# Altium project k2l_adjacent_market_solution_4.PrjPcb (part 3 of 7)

## Sheet k2l_soc_09.SchDoc
size 431 x 279 mm; Date: Not shown in title block; ApprovedBy: Not shown in title block; CheckedBy: Not shown in title block; Author: Not shown in title block; CompanyName: Not shown in title block; Engineer: Not shown in title block; Organization: Not shown in title block; Address1: Not shown in title block; Address2: Not shown in title block; Address3: Not shown in title block; Address4: Not shown in title block; DocumentNumber: 15; Revision: Use project parameter SCH_Rev; SheetNumber: 15; SheetTotal: 38; PageSetup: Record=PageOptions¦CenterHorizontal=True¦CenterVertical=True¦PrintScale=1.00¦XCorrection=1.00¦YCorrection=1.00¦PrintKind=0¦BorderSize=5000000¦LeftOffset=0¦BottomOffset=0¦Orientation=2¦PaperLength=1000¦PaperWidth=1000¦Scale=100¦PaperSource=15¦PrintQuality=600¦MediaType=1¦DitherType=10¦PaperKind=Letter¦PrintScaleMode=1
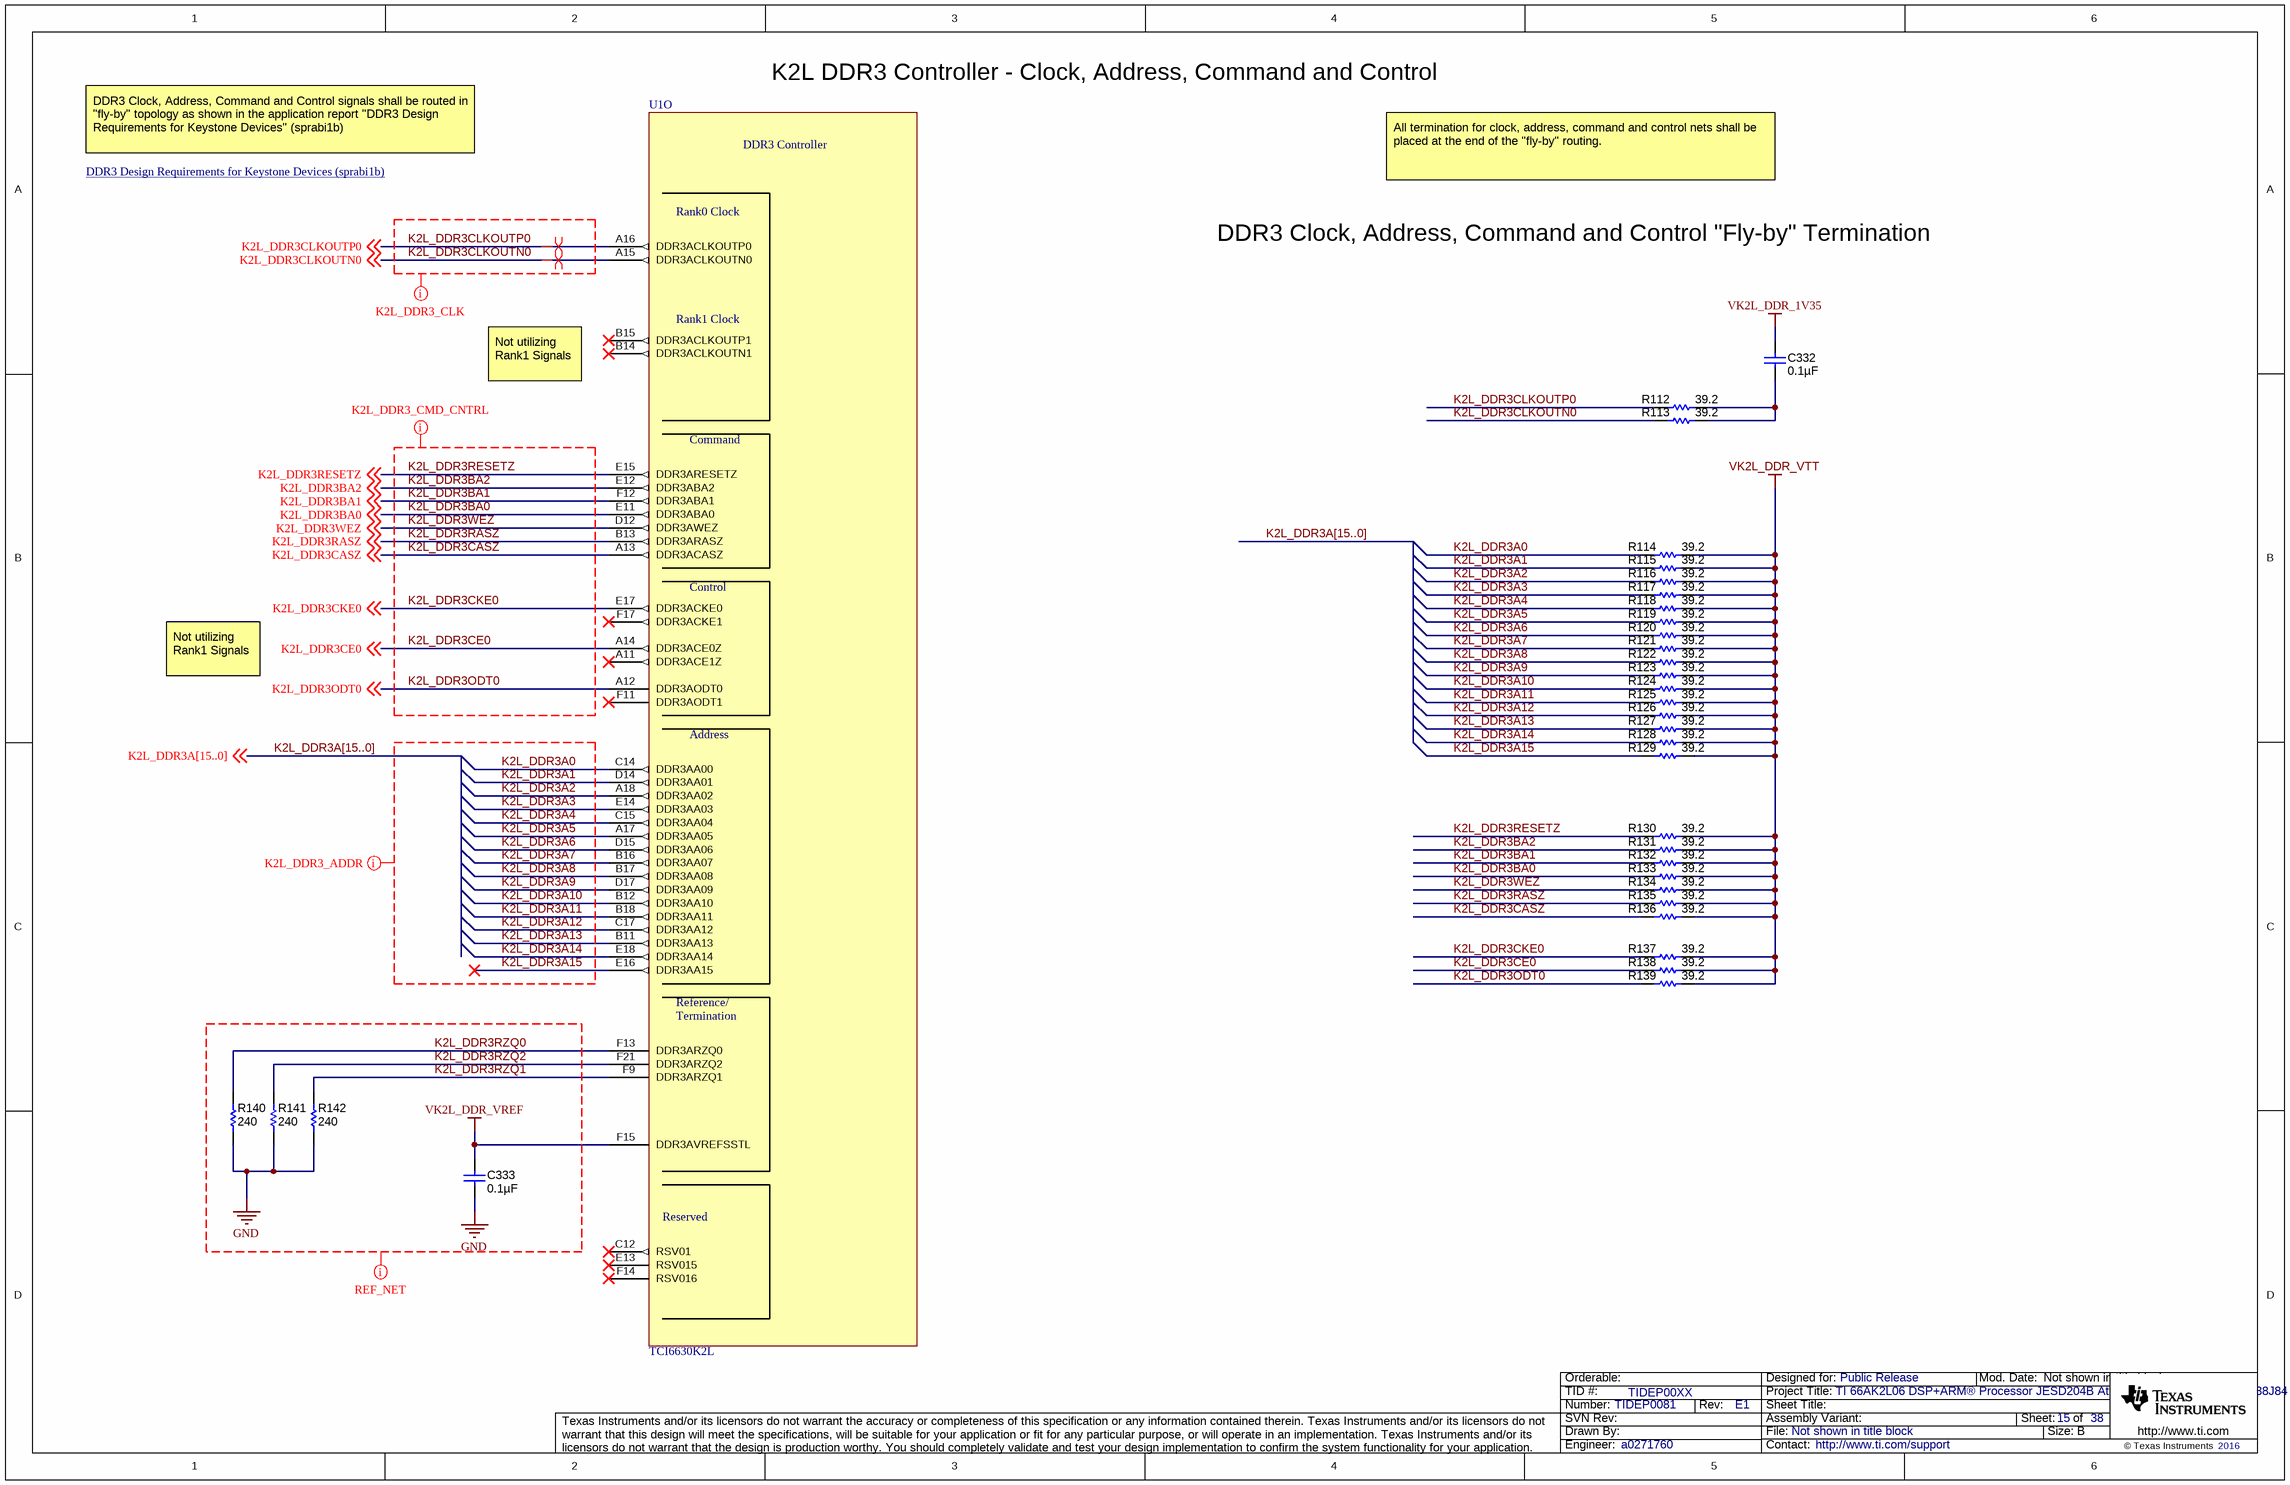
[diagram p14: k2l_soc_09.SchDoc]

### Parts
C332  ValueDisplayed: 0.1µF  [0402]  (hidden comment: GRM152B30J104KE19)
C333  ValueDisplayed: 0.1µF  [0201]  (hidden comment: C0603X5R0J104K030BC)
R112  ValueDisplayed: 39.2  [0402]  (hidden comment: CRCW040239R2FKED)
R113  ValueDisplayed: 39.2  [0402]  (hidden comment: CRCW040239R2FKED)
R114  ValueDisplayed: 39.2  [0402]  (hidden comment: CRCW040239R2FKED)
R115  ValueDisplayed: 39.2  [0402]  (hidden comment: CRCW040239R2FKED)
R116  ValueDisplayed: 39.2  [0402]  (hidden comment: CRCW040239R2FKED)
R117  ValueDisplayed: 39.2  [0402]  (hidden comment: CRCW040239R2FKED)
R118  ValueDisplayed: 39.2  [0402]  (hidden comment: CRCW040239R2FKED)
R119  ValueDisplayed: 39.2  [0402]  (hidden comment: CRCW040239R2FKED)
R120  ValueDisplayed: 39.2  [0402]  (hidden comment: CRCW040239R2FKED)
R121  ValueDisplayed: 39.2  [0402]  (hidden comment: CRCW040239R2FKED)
R122  ValueDisplayed: 39.2  [0402]  (hidden comment: CRCW040239R2FKED)
R123  ValueDisplayed: 39.2  [0402]  (hidden comment: CRCW040239R2FKED)
R124  ValueDisplayed: 39.2  [0402]  (hidden comment: CRCW040239R2FKED)
R125  ValueDisplayed: 39.2  [0402]  (hidden comment: CRCW040239R2FKED)
R126  ValueDisplayed: 39.2  [0402]  (hidden comment: CRCW040239R2FKED)
R127  ValueDisplayed: 39.2  [0402]  (hidden comment: CRCW040239R2FKED)
R128  ValueDisplayed: 39.2  [0402]  (hidden comment: CRCW040239R2FKED)
R129  ValueDisplayed: 39.2  [0402]  (hidden comment: CRCW040239R2FKED)
R130  ValueDisplayed: 39.2  [0402]  (hidden comment: CRCW040239R2FKED)
R131  ValueDisplayed: 39.2  [0402]  (hidden comment: CRCW040239R2FKED)
R132  ValueDisplayed: 39.2  [0402]  (hidden comment: CRCW040239R2FKED)
R133  ValueDisplayed: 39.2  [0402]  (hidden comment: CRCW040239R2FKED)
R134  ValueDisplayed: 39.2  [0402]  (hidden comment: CRCW040239R2FKED)
R135  ValueDisplayed: 39.2  [0402]  (hidden comment: CRCW040239R2FKED)
R136  ValueDisplayed: 39.2  [0402]  (hidden comment: CRCW040239R2FKED)
R137  ValueDisplayed: 39.2  [0402]  (hidden comment: CRCW040239R2FKED)
R138  ValueDisplayed: 39.2  [0402]  (hidden comment: CRCW040239R2FKED)
R139  ValueDisplayed: 39.2  [0402]  (hidden comment: CRCW040239R2FKED)
R140  ValueDisplayed: 240  [0402]  (hidden comment: CRCW0402240RJNED)
R141  ValueDisplayed: 240  [0402]  (hidden comment: CRCW0402240RJNED)
R142  ValueDisplayed: 240  [0402]  (hidden comment: CRCW0402240RJNED)
U1  TCI6630K2L  [BGA900C80P30X30_2500X2500X355]  (part O of 24)

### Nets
GND: C333.2 R140.1 R141.1 R142.1  [project net DAC_OUT0N_T1]
VK2L_DDR_1V35: C332.1
VK2L_DDR_VREF: C333.1 U1.F15(DDR3AVREFSSTL)
VK2L_DDR_VTT: R114.2 R115.2 R116.2 R117.2 R118.2 R119.2 R120.2 R121.2 R122.2 R123.2 R124.2 R125.2 R126.2 R127.2 R128.2 R129.2 R130.2 R131.2 R132.2 R133.2 R134.2 R135.2 R136.2 R137.2 R138.2 R139.2
K2L_DDR3A0: R114.1 U1.C14(DDR3AA00)
K2L_DDR3A1: R115.1 U1.D14(DDR3AA01)
K2L_DDR3A2: R116.1 U1.A18(DDR3AA02)
K2L_DDR3A3: R117.1 U1.E14(DDR3AA03)
K2L_DDR3A4: R118.1 U1.C15(DDR3AA04)
K2L_DDR3A5: R119.1 U1.A17(DDR3AA05)
K2L_DDR3A6: R120.1 U1.D15(DDR3AA06)
K2L_DDR3A7: R121.1 U1.B16(DDR3AA07)
K2L_DDR3A8: R122.1 U1.B17(DDR3AA08)
K2L_DDR3A9: R123.1 U1.D17(DDR3AA09)
K2L_DDR3A10: R124.1 U1.B12(DDR3AA10)
K2L_DDR3A11: R125.1 U1.B18(DDR3AA11)
K2L_DDR3A12: R126.1 U1.C17(DDR3AA12)
K2L_DDR3A13: R127.1 U1.B11(DDR3AA13)
K2L_DDR3A14: R128.1 U1.E18(DDR3AA14)
K2L_DDR3A15: R129.1 U1.E16(DDR3AA15)
K2L_DDR3BA0: R133.1 U1.E11(DDR3ABA0) ; off-sheet K2L_DDR3BA0
K2L_DDR3BA1: R132.1 U1.F12(DDR3ABA1) ; off-sheet K2L_DDR3BA1
K2L_DDR3BA2: R131.1 U1.E12(DDR3ABA2) ; off-sheet K2L_DDR3BA2
K2L_DDR3CASZ: R136.1 U1.A13(DDR3ACASZ) ; off-sheet K2L_DDR3CASZ
K2L_DDR3CE0: R138.1 U1.A14(DDR3ACE0Z) ; off-sheet K2L_DDR3CE0
K2L_DDR3CKE0: R137.1 U1.E17(DDR3ACKE0) ; off-sheet K2L_DDR3CKE0
K2L_DDR3CLKOUTN0: R113.1 U1.A15(DDR3ACLKOUTN0) ; off-sheet K2L_DDR3CLKOUTN0
K2L_DDR3CLKOUTP0: R112.1 U1.A16(DDR3ACLKOUTP0) ; off-sheet K2L_DDR3CLKOUTP0
K2L_DDR3ODT0: R139.1 U1.A12(DDR3AODT0) ; off-sheet K2L_DDR3ODT0
K2L_DDR3RASZ: R135.1 U1.B13(DDR3ARASZ) ; off-sheet K2L_DDR3RASZ
K2L_DDR3RESETZ: R130.1 U1.E15(DDR3ARESETZ) ; off-sheet K2L_DDR3RESETZ
K2L_DDR3RZQ0: R140.2 U1.F13(DDR3ARZQ0)
K2L_DDR3RZQ1: R142.2 U1.F9(DDR3ARZQ1)
K2L_DDR3RZQ2: R141.2 U1.F21(DDR3ARZQ2)
K2L_DDR3WEZ: R134.1 U1.D12(DDR3AWEZ) ; off-sheet K2L_DDR3WEZ
NetC332_2: C332.2 R112.2 R113.2

Not connected (* = marked no-connect by the designer): U1 A11(DDR3ACE1Z)* B14(DDR3ACLKOUTN1)* B15(DDR3ACLKOUTP1)* C12(RSV01)* E13(RSV015)* F11(DDR3AODT1)* F14(RSV016)* F17(DDR3ACKE1)*

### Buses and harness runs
bus K2L_DDR3A[15..0]

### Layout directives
differential pair: K2L_DDR3CLKOUTN0, K2L_DDR3CLKOUTP0
net class Undefined: GND, K2L_DDR3A0, K2L_DDR3A1, K2L_DDR3A2, K2L_DDR3A3, K2L_DDR3A4, K2L_DDR3A5, K2L_DDR3A6, K2L_DDR3A7, K2L_DDR3A8, K2L_DDR3A9, K2L_DDR3A10, K2L_DDR3A11, K2L_DDR3A12, K2L_DDR3A13, K2L_DDR3A14, K2L_DDR3A15, K2L_DDR3BA0, K2L_DDR3BA1, K2L_DDR3BA2, K2L_DDR3CASZ, K2L_DDR3CE0, K2L_DDR3CKE0, K2L_DDR3CLKOUTN0, K2L_DDR3CLKOUTP0, K2L_DDR3ODT0, K2L_DDR3RASZ, K2L_DDR3RESETZ, K2L_DDR3RZQ0, K2L_DDR3RZQ1, K2L_DDR3RZQ2, K2L_DDR3WEZ, VK2L_DDR_VREF

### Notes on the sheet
- K2L DDR3 Controller - Clock, Address, Command and Control
- DDR3 Clock, Address, Command and Control signals shall be routed in "fly-by" topology as shown in the application report "DDR3 Design Requirements for Keystone Devices" (sprabi1b)
- DDR3 Design Requirements for Keystone Devices (sprabi1b) <http://www.ti.com/lit/an/sprabi1b/sprabi1b.pdf>
- All termination for clock, address, command and control nets shall be placed at the end of the "fly-by" routing.
- DDR3 Clock, Address, Command and Control "Fly-by" Termination
- Not utilizing Rank1 Signals

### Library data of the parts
C332 = GRM152B30J104KE19: CAP, CERM, 0.1 µF, 6.3 V, +/- 10%, B, 0402; Manufacturer: MuRata; Polarized: N; CompType: Capacitor; Value: 0.1uF; U/M: EA; Cap_F: 0.0000001; Tolerance_%: 10; Value1: Unknown; VDC_V: 6.3; Value2: 6.3V; TaMin_C: -25; TaMax_C: 85
C333 = C0603X5R0J104K030BC: CAP, CERM, 0.1 µF, 6.3 V, +/- 10%, X5R, 0201; Manufacturer: TDK; Polarized: N; CompType: Capacitor; Value: 0.1uF; U/M: EA; Cap_F: 0.0000001; Tolerance_%: 10; Value1: Unknown; VDC_V: 6.3; Value2: 6.3V; TaMin_C: -55; TaMax_C: 85
R112-R139 = CRCW040239R2FKED: RES, 39.2, 1%, 0.063 W, 0402; Manufacturer: Vishay-Dale; CompType: Resistor; Value: 39.2; Value_Code: 39R2; Tolerance_%: 1; Power_W: 0.063; Value2: 0.063W; VDC_V: 50; TempCo: 100 ppm/C; EIA_Code: E96; U/M: EA
R140-R142 = CRCW0402240RJNED: RES, 240, 5%, 0.063 W, 0402; Manufacturer: Vishay-Dale; CompType: Resistor; Value: 240; Value_Code: 240R; Tolerance_%: 5; Power_W: 0.063; Value2: 0.063W; VDC_V: 50; TempCo: 200 ppm/C; EIA_Code: E24; U/M: EA
U1 = lamarr_soc_TCI6630K2L: Smallcell Baseband Processor with 4 C66x DSP Cores / 2 ARM A15 Cores / JESD / CPRI...etc

## Sheet k2l_soc_09_1.SchDoc
size 431 x 279 mm; Date: Not shown in title block; ApprovedBy: Not shown in title block; CheckedBy: Not shown in title block; Author: Not shown in title block; CompanyName: Not shown in title block; Engineer: Not shown in title block; Organization: Not shown in title block; Address1: Not shown in title block; Address2: Not shown in title block; Address3: Not shown in title block; Address4: Not shown in title block; DocumentNumber: 16; Revision: Use project parameter SCH_Rev; SheetNumber: 16; SheetTotal: 38; PageSetup: Record=PageOptions¦CenterHorizontal=True¦CenterVertical=True¦PrintScale=1.00¦XCorrection=1.00¦YCorrection=1.00¦PrintKind=0¦BorderSize=5000000¦LeftOffset=0¦BottomOffset=0¦Orientation=2¦PaperLength=1000¦PaperWidth=1000¦Scale=100¦PaperSource=15¦PrintQuality=600¦MediaType=1¦DitherType=10¦PaperKind=Letter¦PrintScaleMode=1
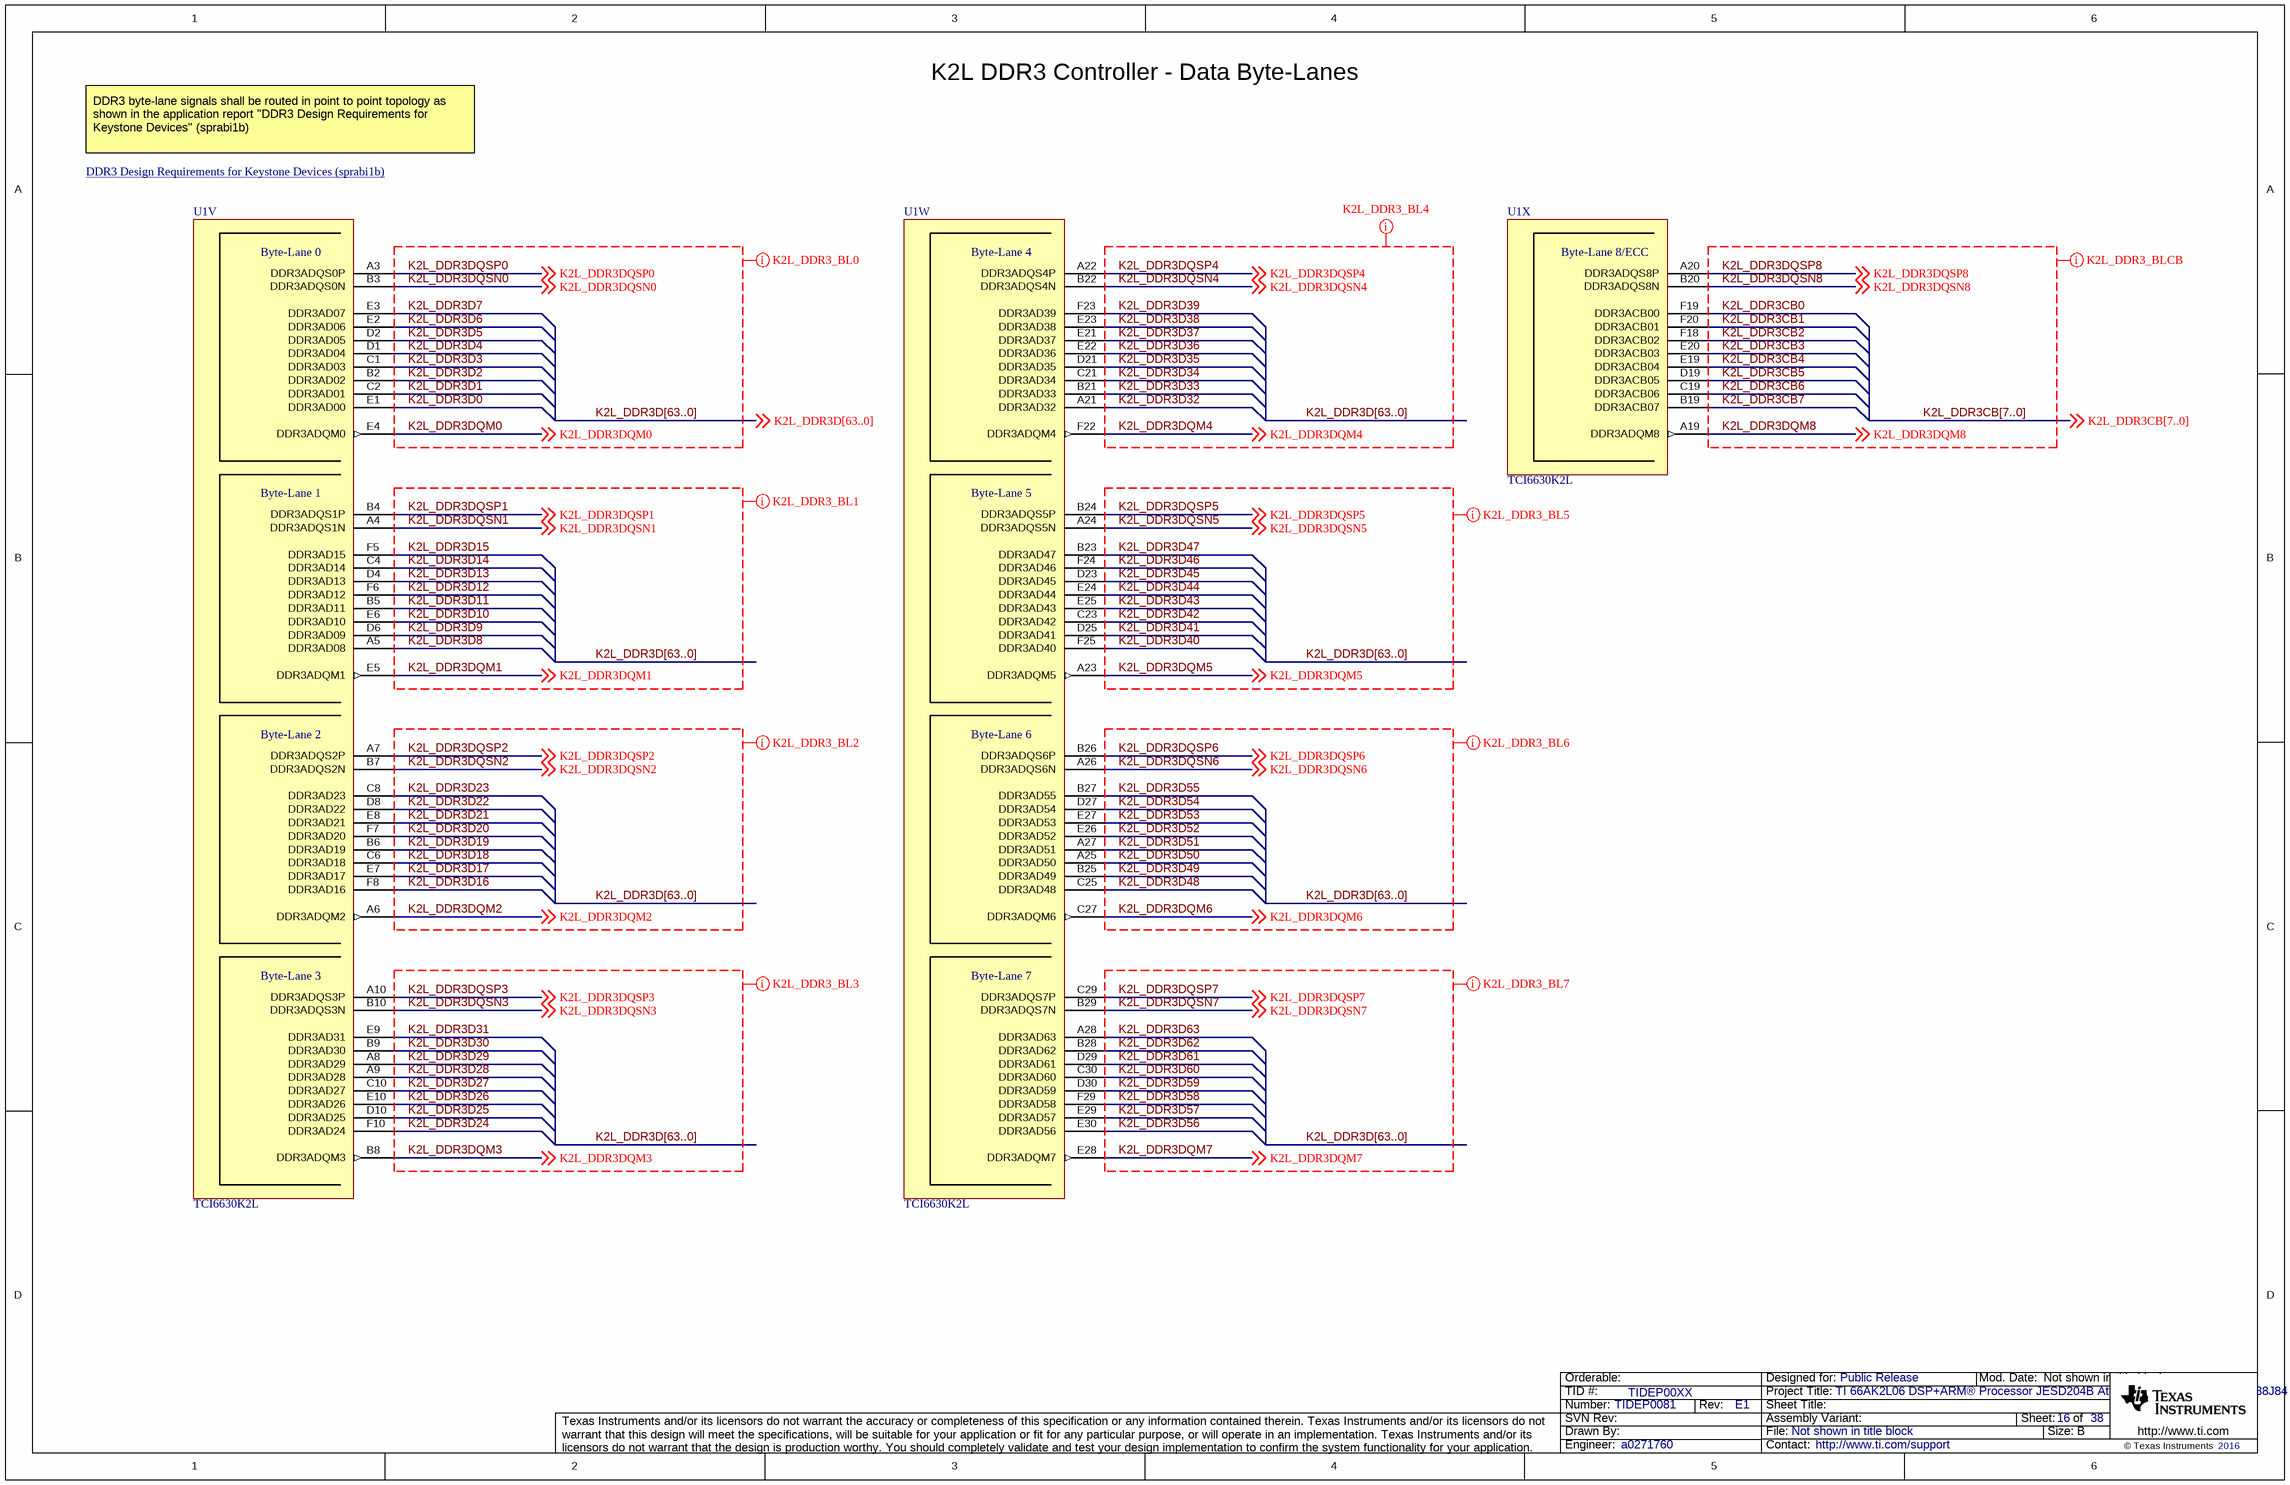
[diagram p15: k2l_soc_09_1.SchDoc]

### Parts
U1  TCI6630K2L  [BGA900C80P30X30_2500X2500X355]  (parts V,W,X of 24)

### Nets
K2L_DDR3CB0: U1.F19(DDR3ACB00)
K2L_DDR3CB1: U1.F20(DDR3ACB01)
K2L_DDR3CB2: U1.F18(DDR3ACB02)
K2L_DDR3CB3: U1.E20(DDR3ACB03)
K2L_DDR3CB4: U1.E19(DDR3ACB04)
K2L_DDR3CB5: U1.D19(DDR3ACB05)
K2L_DDR3CB6: U1.C19(DDR3ACB06)
K2L_DDR3CB7: U1.B19(DDR3ACB07)
K2L_DDR3D0: U1.E1(DDR3AD00)
K2L_DDR3D1: U1.C2(DDR3AD01)
K2L_DDR3D2: U1.B2(DDR3AD02)
K2L_DDR3D3: U1.C1(DDR3AD03)
K2L_DDR3D4: U1.D1(DDR3AD04)
K2L_DDR3D5: U1.D2(DDR3AD05)
K2L_DDR3D6: U1.E2(DDR3AD06)
K2L_DDR3D7: U1.E3(DDR3AD07)
K2L_DDR3D8: U1.A5(DDR3AD08)
K2L_DDR3D9: U1.D6(DDR3AD09)
K2L_DDR3D10: U1.E6(DDR3AD10)
K2L_DDR3D11: U1.B5(DDR3AD11)
K2L_DDR3D12: U1.F6(DDR3AD12)
K2L_DDR3D13: U1.D4(DDR3AD13)
K2L_DDR3D14: U1.C4(DDR3AD14)
K2L_DDR3D15: U1.F5(DDR3AD15)
K2L_DDR3D16: U1.F8(DDR3AD16)
K2L_DDR3D17: U1.E7(DDR3AD17)
K2L_DDR3D18: U1.C6(DDR3AD18)
K2L_DDR3D19: U1.B6(DDR3AD19)
K2L_DDR3D20: U1.F7(DDR3AD20)
K2L_DDR3D21: U1.E8(DDR3AD21)
K2L_DDR3D22: U1.D8(DDR3AD22)
K2L_DDR3D23: U1.C8(DDR3AD23)
K2L_DDR3D24: U1.F10(DDR3AD24)
K2L_DDR3D25: U1.D10(DDR3AD25)
K2L_DDR3D26: U1.E10(DDR3AD26)
K2L_DDR3D27: U1.C10(DDR3AD27)
K2L_DDR3D28: U1.A9(DDR3AD28)
K2L_DDR3D29: U1.A8(DDR3AD29)
K2L_DDR3D30: U1.B9(DDR3AD30)
K2L_DDR3D31: U1.E9(DDR3AD31)
K2L_DDR3D32: U1.A21(DDR3AD32)
K2L_DDR3D33: U1.B21(DDR3AD33)
K2L_DDR3D34: U1.C21(DDR3AD34)
K2L_DDR3D35: U1.D21(DDR3AD35)
K2L_DDR3D36: U1.E22(DDR3AD36)
K2L_DDR3D37: U1.E21(DDR3AD37)
K2L_DDR3D38: U1.E23(DDR3AD38)
K2L_DDR3D39: U1.F23(DDR3AD39)
K2L_DDR3D40: U1.F25(DDR3AD40)
K2L_DDR3D41: U1.D25(DDR3AD41)
K2L_DDR3D42: U1.C23(DDR3AD42)
K2L_DDR3D43: U1.E25(DDR3AD43)
K2L_DDR3D44: U1.E24(DDR3AD44)
K2L_DDR3D45: U1.D23(DDR3AD45)
K2L_DDR3D46: U1.F24(DDR3AD46)
K2L_DDR3D47: U1.B23(DDR3AD47)
K2L_DDR3D48: U1.C25(DDR3AD48)
K2L_DDR3D49: U1.B25(DDR3AD49)
K2L_DDR3D50: U1.A25(DDR3AD50)
K2L_DDR3D51: U1.A27(DDR3AD51)
K2L_DDR3D52: U1.E26(DDR3AD52)
K2L_DDR3D53: U1.E27(DDR3AD53)
K2L_DDR3D54: U1.D27(DDR3AD54)
K2L_DDR3D55: U1.B27(DDR3AD55)
K2L_DDR3D56: U1.E30(DDR3AD56)
K2L_DDR3D57: U1.E29(DDR3AD57)
K2L_DDR3D58: U1.F29(DDR3AD58)
K2L_DDR3D59: U1.D30(DDR3AD59)
K2L_DDR3D60: U1.C30(DDR3AD60)
K2L_DDR3D61: U1.D29(DDR3AD61)
K2L_DDR3D62: U1.B28(DDR3AD62)
K2L_DDR3D63: U1.A28(DDR3AD63)
K2L_DDR3DQM0: U1.E4(DDR3ADQM0) ; off-sheet K2L_DDR3DQM0
K2L_DDR3DQM1: U1.E5(DDR3ADQM1) ; off-sheet K2L_DDR3DQM1
K2L_DDR3DQM2: U1.A6(DDR3ADQM2) ; off-sheet K2L_DDR3DQM2
K2L_DDR3DQM3: U1.B8(DDR3ADQM3) ; off-sheet K2L_DDR3DQM3
K2L_DDR3DQM4: U1.F22(DDR3ADQM4) ; off-sheet K2L_DDR3DQM4
K2L_DDR3DQM5: U1.A23(DDR3ADQM5) ; off-sheet K2L_DDR3DQM5
K2L_DDR3DQM6: U1.C27(DDR3ADQM6) ; off-sheet K2L_DDR3DQM6
K2L_DDR3DQM7: U1.E28(DDR3ADQM7) ; off-sheet K2L_DDR3DQM7
K2L_DDR3DQM8: U1.A19(DDR3ADQM8) ; off-sheet K2L_DDR3DQM8
K2L_DDR3DQSN0: U1.B3(DDR3ADQS0N) ; off-sheet K2L_DDR3DQSN0
K2L_DDR3DQSN1: U1.A4(DDR3ADQS1N) ; off-sheet K2L_DDR3DQSN1
K2L_DDR3DQSN2: U1.B7(DDR3ADQS2N) ; off-sheet K2L_DDR3DQSN2
K2L_DDR3DQSN3: U1.B10(DDR3ADQS3N) ; off-sheet K2L_DDR3DQSN3
K2L_DDR3DQSN4: U1.B22(DDR3ADQS4N) ; off-sheet K2L_DDR3DQSN4
K2L_DDR3DQSN5: U1.A24(DDR3ADQS5N) ; off-sheet K2L_DDR3DQSN5
K2L_DDR3DQSN6: U1.A26(DDR3ADQS6N) ; off-sheet K2L_DDR3DQSN6
K2L_DDR3DQSN7: U1.B29(DDR3ADQS7N) ; off-sheet K2L_DDR3DQSN7
K2L_DDR3DQSN8: U1.B20(DDR3ADQS8N) ; off-sheet K2L_DDR3DQSN8
K2L_DDR3DQSP0: U1.A3(DDR3ADQS0P) ; off-sheet K2L_DDR3DQSP0
K2L_DDR3DQSP1: U1.B4(DDR3ADQS1P) ; off-sheet K2L_DDR3DQSP1
K2L_DDR3DQSP2: U1.A7(DDR3ADQS2P) ; off-sheet K2L_DDR3DQSP2
K2L_DDR3DQSP3: U1.A10(DDR3ADQS3P) ; off-sheet K2L_DDR3DQSP3
K2L_DDR3DQSP4: U1.A22(DDR3ADQS4P) ; off-sheet K2L_DDR3DQSP4
K2L_DDR3DQSP5: U1.B24(DDR3ADQS5P) ; off-sheet K2L_DDR3DQSP5
K2L_DDR3DQSP6: U1.B26(DDR3ADQS6P) ; off-sheet K2L_DDR3DQSP6
K2L_DDR3DQSP7: U1.C29(DDR3ADQS7P) ; off-sheet K2L_DDR3DQSP7
K2L_DDR3DQSP8: U1.A20(DDR3ADQS8P) ; off-sheet K2L_DDR3DQSP8

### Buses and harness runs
bus K2L_DDR3CB[7..0]
bus K2L_DDR3D[63..0]

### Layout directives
net class Undefined: K2L_DDR3CB0, K2L_DDR3CB1, K2L_DDR3CB2, K2L_DDR3CB3, K2L_DDR3CB4, K2L_DDR3CB5, K2L_DDR3CB6, K2L_DDR3CB7, K2L_DDR3CB[7..0], K2L_DDR3D0, K2L_DDR3D1, K2L_DDR3D2, K2L_DDR3D3, K2L_DDR3D4, K2L_DDR3D5, K2L_DDR3D6, K2L_DDR3D7, K2L_DDR3D8, K2L_DDR3D9, K2L_DDR3D10, K2L_DDR3D11, K2L_DDR3D12, K2L_DDR3D13, K2L_DDR3D14, K2L_DDR3D15, K2L_DDR3D16, K2L_DDR3D17, K2L_DDR3D18, K2L_DDR3D19, K2L_DDR3D20, K2L_DDR3D21, K2L_DDR3D22, K2L_DDR3D23, K2L_DDR3D24, K2L_DDR3D25, K2L_DDR3D26, K2L_DDR3D27, K2L_DDR3D28, K2L_DDR3D29, K2L_DDR3D30, K2L_DDR3D31, K2L_DDR3D32, K2L_DDR3D33, K2L_DDR3D34, K2L_DDR3D35, K2L_DDR3D36, K2L_DDR3D37, K2L_DDR3D38, K2L_DDR3D39, K2L_DDR3D40, K2L_DDR3D41, K2L_DDR3D42, K2L_DDR3D43, K2L_DDR3D44, K2L_DDR3D45, K2L_DDR3D46, K2L_DDR3D47, K2L_DDR3D48, K2L_DDR3D49, K2L_DDR3D50, K2L_DDR3D51, K2L_DDR3D52, K2L_DDR3D53, K2L_DDR3D54, K2L_DDR3D55, K2L_DDR3D56, K2L_DDR3D57, K2L_DDR3D58, K2L_DDR3D59, K2L_DDR3D60, K2L_DDR3D61, K2L_DDR3D62, K2L_DDR3D63, K2L_DDR3D[63..0], K2L_DDR3DQM0, K2L_DDR3DQM1, K2L_DDR3DQM2, K2L_DDR3DQM3, K2L_DDR3DQM4, K2L_DDR3DQM5, K2L_DDR3DQM6, K2L_DDR3DQM7, K2L_DDR3DQM8, K2L_DDR3DQSN0, K2L_DDR3DQSN1, K2L_DDR3DQSN2, K2L_DDR3DQSN3, K2L_DDR3DQSN4, K2L_DDR3DQSN5, K2L_DDR3DQSN6, K2L_DDR3DQSN7, K2L_DDR3DQSN8, K2L_DDR3DQSP0, K2L_DDR3DQSP1, K2L_DDR3DQSP2, K2L_DDR3DQSP3, K2L_DDR3DQSP4, K2L_DDR3DQSP5, K2L_DDR3DQSP6, K2L_DDR3DQSP7, K2L_DDR3DQSP8

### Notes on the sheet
- K2L DDR3 Controller - Data Byte-Lanes
- DDR3 byte-lane signals shall be routed in point to point topology as shown in the application report "DDR3 Design Requirements for Keystone Devices" (sprabi1b)
- DDR3 Design Requirements for Keystone Devices (sprabi1b) <http://www.ti.com/lit/an/sprabi1b/sprabi1b.pdf>

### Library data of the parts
U1 = lamarr_soc_TCI6630K2L: as U1 on sheet k2l_soc_09

## Sheet k2l_soc_09_2.SchDoc
size 431 x 279 mm; Date: Not shown in title block; ApprovedBy: Not shown in title block; CheckedBy: Not shown in title block; Author: Not shown in title block; CompanyName: Not shown in title block; Engineer: Not shown in title block; Organization: Not shown in title block; Address1: Not shown in title block; Address2: Not shown in title block; Address3: Not shown in title block; Address4: Not shown in title block; DocumentNumber: 17; Revision: Use project parameter SCH_Rev; SheetNumber: 17; SheetTotal: 38; PageSetup: Record=PageOptions¦CenterHorizontal=True¦CenterVertical=True¦PrintScale=1.00¦XCorrection=1.00¦YCorrection=1.00¦PrintKind=0¦BorderSize=5000000¦LeftOffset=0¦BottomOffset=0¦Orientation=2¦PaperLength=1000¦PaperWidth=1000¦Scale=100¦PaperSource=15¦PrintQuality=600¦MediaType=1¦DitherType=10¦PaperKind=Letter¦PrintScaleMode=1
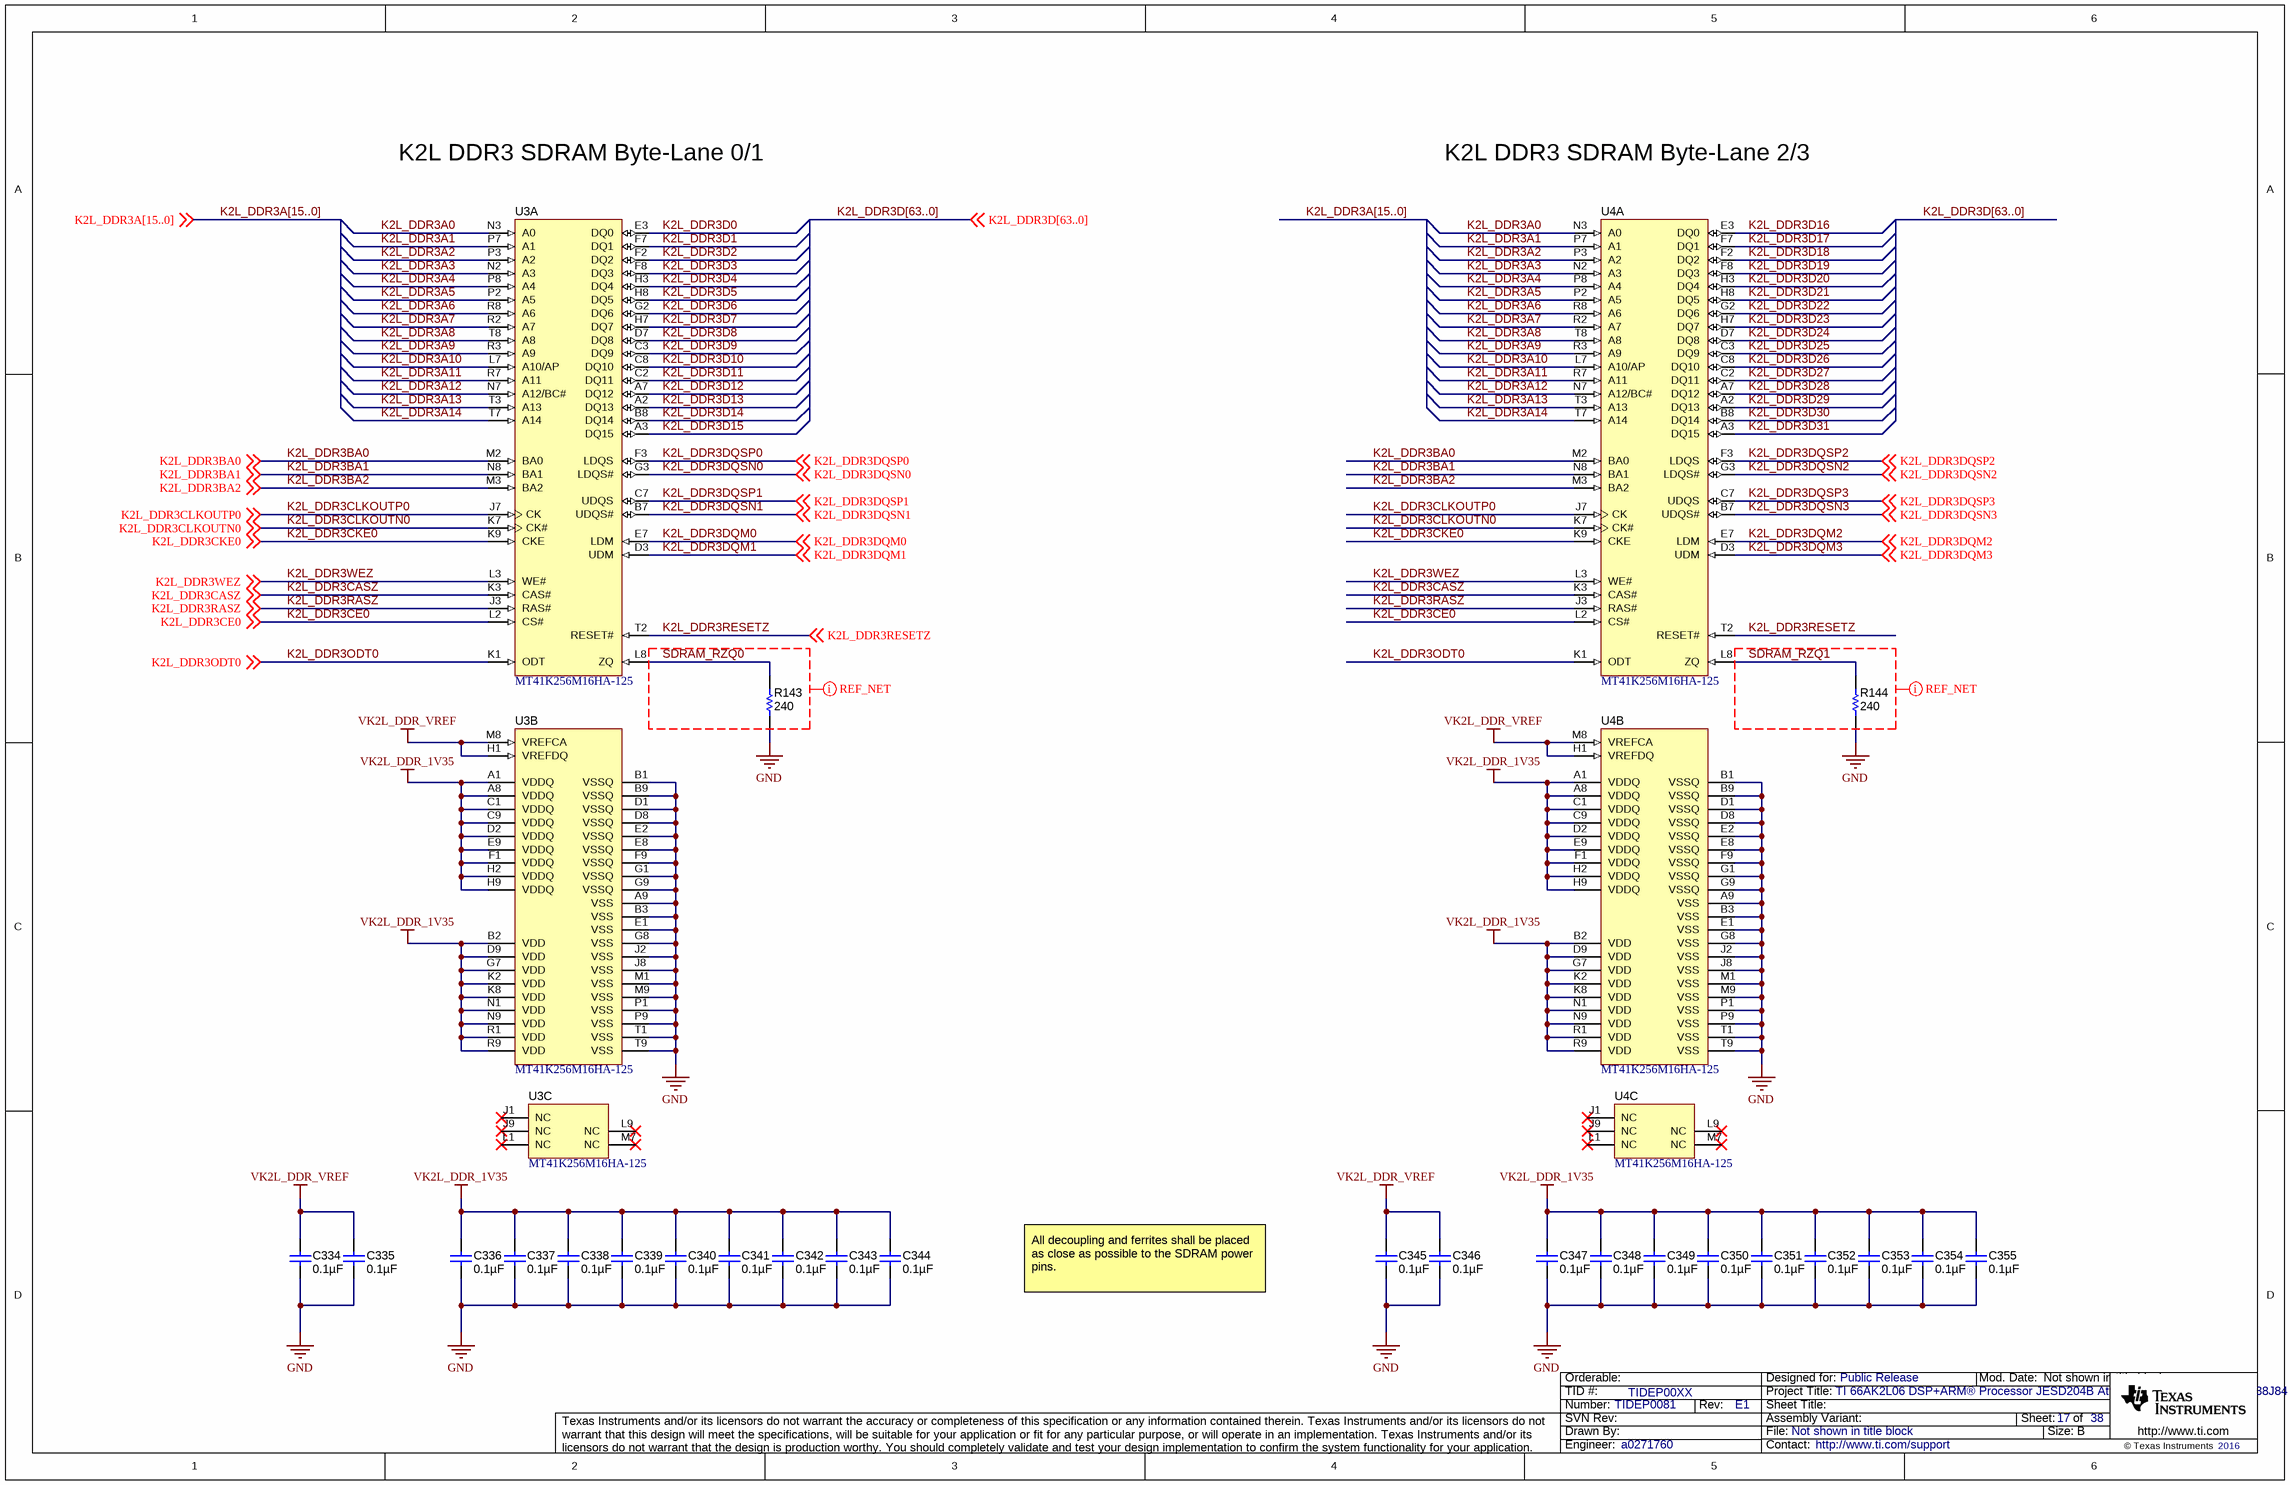
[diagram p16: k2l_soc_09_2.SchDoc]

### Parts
C334  ValueDisplayed: 0.1µF  [0201]  (hidden comment: C0603X5R0J104K030BC)
C335  ValueDisplayed: 0.1µF  [0201]  (hidden comment: C0603X5R0J104K030BC)
C336  ValueDisplayed: 0.1µF  [0402]  (hidden comment: GRM152B30J104KE19)
C337  ValueDisplayed: 0.1µF  [0402]  (hidden comment: GRM152B30J104KE19)
C338  ValueDisplayed: 0.1µF  [0402]  (hidden comment: GRM152B30J104KE19)
C339  ValueDisplayed: 0.1µF  [0402]  (hidden comment: GRM152B30J104KE19)
C340  ValueDisplayed: 0.1µF  [0402]  (hidden comment: GRM152B30J104KE19)
C341  ValueDisplayed: 0.1µF  [0402]  (hidden comment: GRM152B30J104KE19)
C342  ValueDisplayed: 0.1µF  [0402]  (hidden comment: GRM152B30J104KE19)
C343  ValueDisplayed: 0.1µF  [0402]  (hidden comment: GRM152B30J104KE19)
C344  ValueDisplayed: 0.1µF  [0402]  (hidden comment: GRM152B30J104KE19)
C345  ValueDisplayed: 0.1µF  [0201]  (hidden comment: C0603X5R0J104K030BC)
C346  ValueDisplayed: 0.1µF  [0201]  (hidden comment: C0603X5R0J104K030BC)
C347  ValueDisplayed: 0.1µF  [0402]  (hidden comment: GRM152B30J104KE19)
C348  ValueDisplayed: 0.1µF  [0402]  (hidden comment: GRM152B30J104KE19)
C349  ValueDisplayed: 0.1µF  [0402]  (hidden comment: GRM152B30J104KE19)
C350  ValueDisplayed: 0.1µF  [0402]  (hidden comment: GRM152B30J104KE19)
C351  ValueDisplayed: 0.1µF  [0402]  (hidden comment: GRM152B30J104KE19)
C352  ValueDisplayed: 0.1µF  [0402]  (hidden comment: GRM152B30J104KE19)
C353  ValueDisplayed: 0.1µF  [0402]  (hidden comment: GRM152B30J104KE19)
C354  ValueDisplayed: 0.1µF  [0402]  (hidden comment: GRM152B30J104KE19)
C355  ValueDisplayed: 0.1µF  [0402]  (hidden comment: GRM152B30J104KE19)
R143  ValueDisplayed: 240  [0402]  (hidden comment: CRCW0402240RJNED)
R144  ValueDisplayed: 240  [0402]  (hidden comment: CRCW0402240RJNED)
U3  MT41K256M16HA-125  [MICT-HA-96]  (parts A,B,C of 3)
U4  MT41K256M16HA-125  [MICT-HA-96]  (parts A,B,C of 3)

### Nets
GND: C334.2 C335.2 C336.2 C337.2 C338.2 C339.2 C340.2 C341.2 C342.2 C343.2 C344.2 C345.2 C346.2 C347.2 C348.2 C349.2 C350.2 C351.2 C352.2 C353.2 C354.2 C355.2 R143.1 R144.1 U3.A9(VSS) U3.B1(VSSQ) U3.B3(VSS) U3.B9(VSSQ) U3.D1(VSSQ) U3.D8(VSSQ) U3.E1(VSS) U3.E2(VSSQ) U3.E8(VSSQ) U3.F9(VSSQ) U3.G1(VSSQ) U3.G8(VSS) U3.G9(VSSQ) U3.J2(VSS) U3.J8(VSS) U3.M1(VSS) U3.M9(VSS) U3.P1(VSS) U3.P9(VSS) U3.T1(VSS) U3.T9(VSS) U4.A9(VSS) U4.B1(VSSQ) U4.B3(VSS) U4.B9(VSSQ) U4.D1(VSSQ) U4.D8(VSSQ) U4.E1(VSS) U4.E2(VSSQ) U4.E8(VSSQ) U4.F9(VSSQ) U4.G1(VSSQ) U4.G8(VSS) U4.G9(VSSQ) U4.J2(VSS) U4.J8(VSS) U4.M1(VSS) U4.M9(VSS) U4.P1(VSS) U4.P9(VSS) U4.T1(VSS) U4.T9(VSS)  [project net DAC_OUT0N_T1]
VK2L_DDR_1V35: C336.1 C337.1 C338.1 C339.1 C340.1 C341.1 C342.1 C343.1 C344.1 C347.1 C348.1 C349.1 C350.1 C351.1 C352.1 C353.1 C354.1 C355.1 U3.A1(VDDQ) U3.A8(VDDQ) U3.B2(VDD) U3.C1(VDDQ) U3.C9(VDDQ) U3.D2(VDDQ) U3.D9(VDD) U3.E9(VDDQ) U3.F1(VDDQ) U3.G7(VDD) U3.H2(VDDQ) U3.H9(VDDQ) U3.K2(VDD) U3.K8(VDD) U3.N1(VDD) U3.N9(VDD) U3.R1(VDD) U3.R9(VDD) U4.A1(VDDQ) U4.A8(VDDQ) U4.B2(VDD) U4.C1(VDDQ) U4.C9(VDDQ) U4.D2(VDDQ) U4.D9(VDD) U4.E9(VDDQ) U4.F1(VDDQ) U4.G7(VDD) U4.H2(VDDQ) U4.H9(VDDQ) U4.K2(VDD) U4.K8(VDD) U4.N1(VDD) U4.N9(VDD) U4.R1(VDD) U4.R9(VDD)
VK2L_DDR_VREF: C334.1 C335.1 C345.1 C346.1 U3.H1(VREFDQ) U3.M8(VREFCA) U4.H1(VREFDQ) U4.M8(VREFCA)
K2L_DDR3A0: U3.N3(A0) U4.N3(A0)
K2L_DDR3A1: U3.P7(A1) U4.P7(A1)
K2L_DDR3A2: U3.P3(A2) U4.P3(A2)
K2L_DDR3A3: U3.N2(A3) U4.N2(A3)
K2L_DDR3A4: U3.P8(A4) U4.P8(A4)
K2L_DDR3A5: U3.P2(A5) U4.P2(A5)
K2L_DDR3A6: U3.R8(A6) U4.R8(A6)
K2L_DDR3A7: U3.R2(A7) U4.R2(A7)
K2L_DDR3A8: U3.T8(A8) U4.T8(A8)
K2L_DDR3A9: U3.R3(A9) U4.R3(A9)
K2L_DDR3A10: U3.L7(A10/AP) U4.L7(A10/AP)
K2L_DDR3A11: U3.R7(A11) U4.R7(A11)
K2L_DDR3A12: U3.N7(A12/BC#) U4.N7(A12/BC#)
K2L_DDR3A13: U3.T3(A13) U4.T3(A13)
K2L_DDR3A14: U3.T7(A14) U4.T7(A14)
K2L_DDR3BA0: U3.M2(BA0) U4.M2(BA0) ; off-sheet K2L_DDR3BA0
K2L_DDR3BA1: U3.N8(BA1) U4.N8(BA1) ; off-sheet K2L_DDR3BA1
K2L_DDR3BA2: U3.M3(BA2) U4.M3(BA2) ; off-sheet K2L_DDR3BA2
K2L_DDR3CASZ: U3.K3(CAS#) U4.K3(CAS#) ; off-sheet K2L_DDR3CASZ
K2L_DDR3CE0: U3.L2(CS#) U4.L2(CS#) ; off-sheet K2L_DDR3CE0
K2L_DDR3CKE0: U3.K9(CKE) U4.K9(CKE) ; off-sheet K2L_DDR3CKE0
K2L_DDR3CLKOUTN0: U3.K7(CK#) U4.K7(CK#) ; off-sheet K2L_DDR3CLKOUTN0
K2L_DDR3CLKOUTP0: U3.J7(CK) U4.J7(CK) ; off-sheet K2L_DDR3CLKOUTP0
K2L_DDR3D0: U3.E3(DQ0)
K2L_DDR3D1: U3.F7(DQ1)
K2L_DDR3D2: U3.F2(DQ2)
K2L_DDR3D3: U3.F8(DQ3)
K2L_DDR3D4: U3.H3(DQ4)
K2L_DDR3D5: U3.H8(DQ5)
K2L_DDR3D6: U3.G2(DQ6)
K2L_DDR3D7: U3.H7(DQ7)
K2L_DDR3D8: U3.D7(DQ8)
K2L_DDR3D9: U3.C3(DQ9)
K2L_DDR3D10: U3.C8(DQ10)
K2L_DDR3D11: U3.C2(DQ11)
K2L_DDR3D12: U3.A7(DQ12)
K2L_DDR3D13: U3.A2(DQ13)
K2L_DDR3D14: U3.B8(DQ14)
K2L_DDR3D15: U3.A3(DQ15)
K2L_DDR3D16: U4.E3(DQ0)
K2L_DDR3D17: U4.F7(DQ1)
K2L_DDR3D18: U4.F2(DQ2)
K2L_DDR3D19: U4.F8(DQ3)
K2L_DDR3D20: U4.H3(DQ4)
K2L_DDR3D21: U4.H8(DQ5)
K2L_DDR3D22: U4.G2(DQ6)
K2L_DDR3D23: U4.H7(DQ7)
K2L_DDR3D24: U4.D7(DQ8)
K2L_DDR3D25: U4.C3(DQ9)
K2L_DDR3D26: U4.C8(DQ10)
K2L_DDR3D27: U4.C2(DQ11)
K2L_DDR3D28: U4.A7(DQ12)
K2L_DDR3D29: U4.A2(DQ13)
K2L_DDR3D30: U4.B8(DQ14)
K2L_DDR3D31: U4.A3(DQ15)
K2L_DDR3DQM0: U3.E7(LDM) ; off-sheet K2L_DDR3DQM0
K2L_DDR3DQM1: U3.D3(UDM) ; off-sheet K2L_DDR3DQM1
K2L_DDR3DQM2: U4.E7(LDM) ; off-sheet K2L_DDR3DQM2
K2L_DDR3DQM3: U4.D3(UDM) ; off-sheet K2L_DDR3DQM3
K2L_DDR3DQSN0: U3.G3(LDQS#) ; off-sheet K2L_DDR3DQSN0
K2L_DDR3DQSN1: U3.B7(UDQS#) ; off-sheet K2L_DDR3DQSN1
K2L_DDR3DQSN2: U4.G3(LDQS#) ; off-sheet K2L_DDR3DQSN2
K2L_DDR3DQSN3: U4.B7(UDQS#) ; off-sheet K2L_DDR3DQSN3
K2L_DDR3DQSP0: U3.F3(LDQS) ; off-sheet K2L_DDR3DQSP0
K2L_DDR3DQSP1: U3.C7(UDQS) ; off-sheet K2L_DDR3DQSP1
K2L_DDR3DQSP2: U4.F3(LDQS) ; off-sheet K2L_DDR3DQSP2
K2L_DDR3DQSP3: U4.C7(UDQS) ; off-sheet K2L_DDR3DQSP3
K2L_DDR3ODT0: U3.K1(ODT) U4.K1(ODT) ; off-sheet K2L_DDR3ODT0
K2L_DDR3RASZ: U3.J3(RAS#) U4.J3(RAS#) ; off-sheet K2L_DDR3RASZ
K2L_DDR3RESETZ: U3.T2(RESET#) U4.T2(RESET#) ; off-sheet K2L_DDR3RESETZ
K2L_DDR3WEZ: U3.L3(WE#) U4.L3(WE#) ; off-sheet K2L_DDR3WEZ
SDRAM_RZQ0: R143.2 U3.L8(ZQ)
SDRAM_RZQ1: R144.2 U4.L8(ZQ)

Not connected (* = marked no-connect by the designer): U3 J1(NC)* J9(NC)* L1(NC)* L9(NC)* M7(NC)*; U4 J1(NC)* J9(NC)* L1(NC)* L9(NC)* M7(NC)*

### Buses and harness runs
bus K2L_DDR3A[15..0]
bus K2L_DDR3D[63..0]

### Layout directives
net class Undefined: SDRAM_RZQ0, SDRAM_RZQ1

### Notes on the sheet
- K2L DDR3 SDRAM Byte-Lane 0/1
- K2L DDR3 SDRAM Byte-Lane 2/3
- All decoupling and ferrites shall be placed as close as possible to the SDRAM power pins.

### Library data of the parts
C334 C335 C345 C346 = C0603X5R0J104K030BC: as C333 on sheet k2l_soc_09
C336-C344 C347-C355 = GRM152B30J104KE19: as C332 on sheet k2l_soc_09
R143 R144 = CRCW0402240RJNED: as R140 on sheet k2l_soc_09
U3 U4 = MT41K256M16HA-125: 4Gb DDR3-1600 SDRAM, 256Mb x 16, 1.25ns, 1.35V, 0 to 95 degC, 96-Ball FBGA, Pb-Free; Manufacturer: Micron; CL: CL = 11; Clock Rate: 800 MHz; Op. Temp.: 0C to +95C

## Sheet k2l_soc_09_3.SchDoc
size 431 x 279 mm; Date: Not shown in title block; ApprovedBy: Not shown in title block; CheckedBy: Not shown in title block; Author: Not shown in title block; CompanyName: Not shown in title block; Engineer: Not shown in title block; Organization: Not shown in title block; Address1: Not shown in title block; Address2: Not shown in title block; Address3: Not shown in title block; Address4: Not shown in title block; DocumentNumber: 18; Revision: Use project parameter SCH_Rev; SheetNumber: 18; SheetTotal: 38; PageSetup: Record=PageOptions¦CenterHorizontal=True¦CenterVertical=True¦PrintScale=1.00¦XCorrection=1.00¦YCorrection=1.00¦PrintKind=0¦BorderSize=5000000¦LeftOffset=0¦BottomOffset=0¦Orientation=2¦PaperLength=1000¦PaperWidth=1000¦Scale=100¦PaperSource=15¦PrintQuality=600¦MediaType=1¦DitherType=10¦PaperKind=Letter¦PrintScaleMode=1
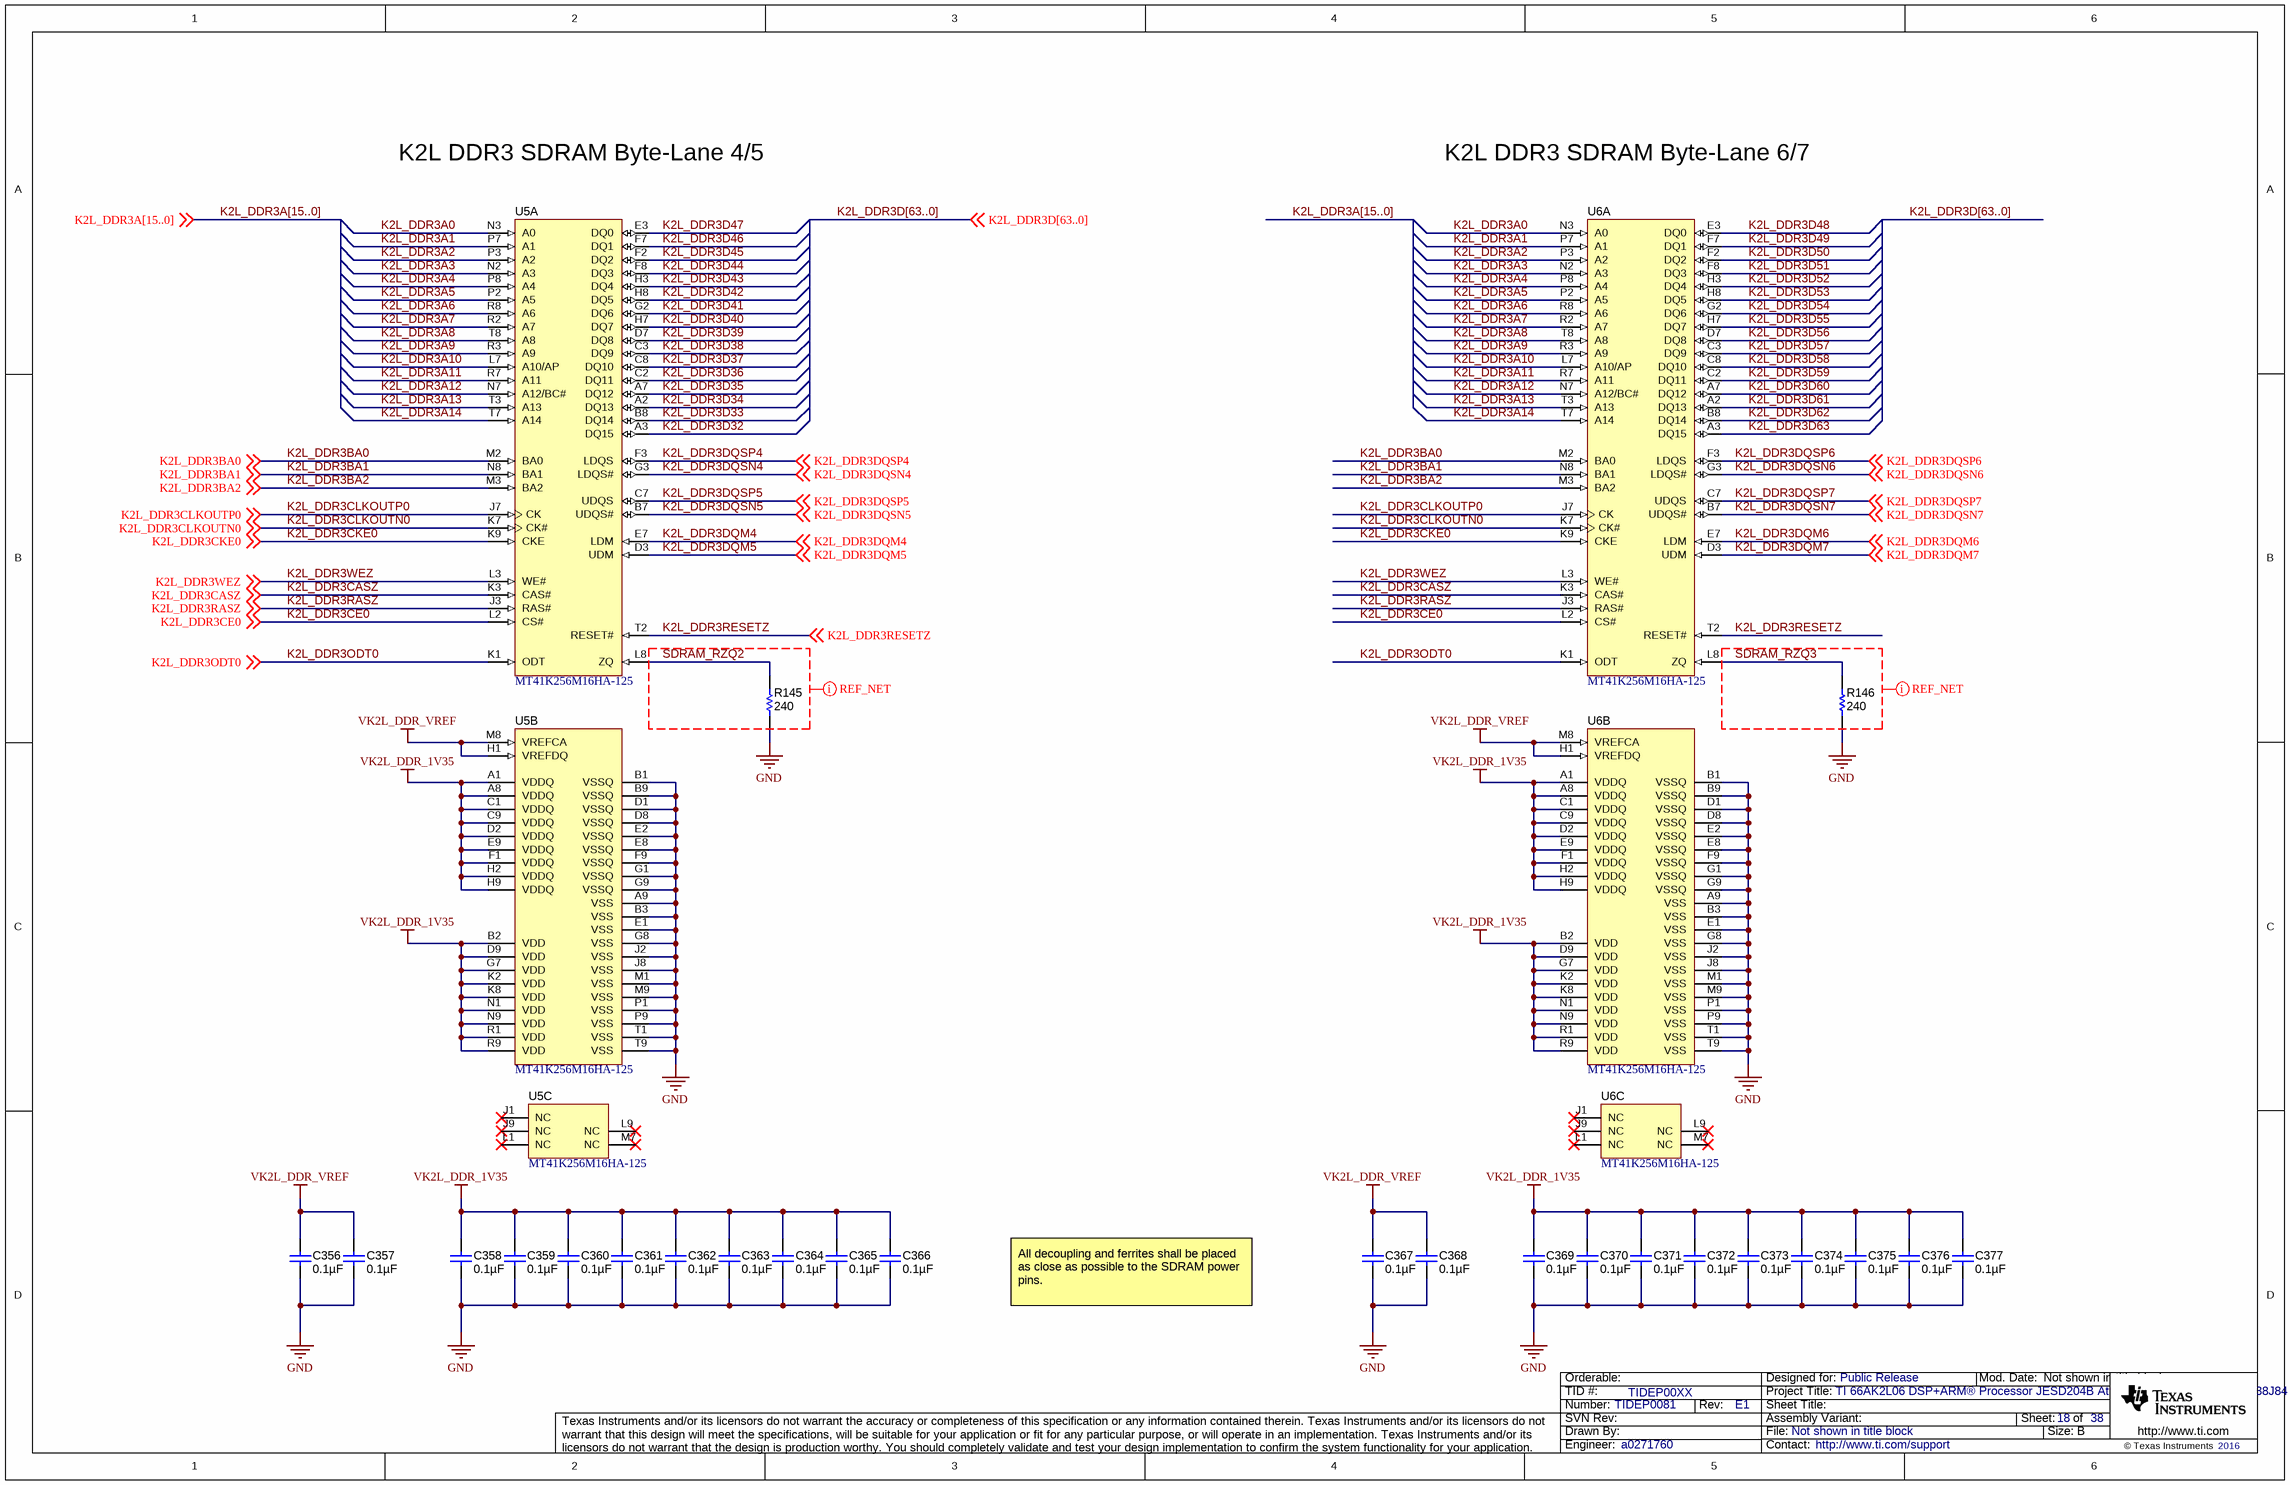
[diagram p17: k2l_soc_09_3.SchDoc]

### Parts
C356  ValueDisplayed: 0.1µF  [0201]  (hidden comment: C0603X5R0J104K030BC)
C357  ValueDisplayed: 0.1µF  [0201]  (hidden comment: C0603X5R0J104K030BC)
C358  ValueDisplayed: 0.1µF  [0402]  (hidden comment: GRM152B30J104KE19)
C359  ValueDisplayed: 0.1µF  [0402]  (hidden comment: GRM152B30J104KE19)
C360  ValueDisplayed: 0.1µF  [0402]  (hidden comment: GRM152B30J104KE19)
C361  ValueDisplayed: 0.1µF  [0402]  (hidden comment: GRM152B30J104KE19)
C362  ValueDisplayed: 0.1µF  [0402]  (hidden comment: GRM152B30J104KE19)
C363  ValueDisplayed: 0.1µF  [0402]  (hidden comment: GRM152B30J104KE19)
C364  ValueDisplayed: 0.1µF  [0402]  (hidden comment: GRM152B30J104KE19)
C365  ValueDisplayed: 0.1µF  [0402]  (hidden comment: GRM152B30J104KE19)
C366  ValueDisplayed: 0.1µF  [0402]  (hidden comment: GRM152B30J104KE19)
C367  ValueDisplayed: 0.1µF  [0201]  (hidden comment: C0603X5R0J104K030BC)
C368  ValueDisplayed: 0.1µF  [0201]  (hidden comment: C0603X5R0J104K030BC)
C369  ValueDisplayed: 0.1µF  [0402]  (hidden comment: GRM152B30J104KE19)
C370  ValueDisplayed: 0.1µF  [0402]  (hidden comment: GRM152B30J104KE19)
C371  ValueDisplayed: 0.1µF  [0402]  (hidden comment: GRM152B30J104KE19)
C372  ValueDisplayed: 0.1µF  [0402]  (hidden comment: GRM152B30J104KE19)
C373  ValueDisplayed: 0.1µF  [0402]  (hidden comment: GRM152B30J104KE19)
C374  ValueDisplayed: 0.1µF  [0402]  (hidden comment: GRM152B30J104KE19)
C375  ValueDisplayed: 0.1µF  [0402]  (hidden comment: GRM152B30J104KE19)
C376  ValueDisplayed: 0.1µF  [0402]  (hidden comment: GRM152B30J104KE19)
C377  ValueDisplayed: 0.1µF  [0402]  (hidden comment: GRM152B30J104KE19)
R145  ValueDisplayed: 240  [0402]  (hidden comment: CRCW0402240RJNED)
R146  ValueDisplayed: 240  [0402]  (hidden comment: CRCW0402240RJNED)
U5  MT41K256M16HA-125  [MICT-HA-96]  (parts A,B,C of 3)
U6  MT41K256M16HA-125  [MICT-HA-96]  (parts A,B,C of 3)

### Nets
GND: C356.2 C357.2 C358.2 C359.2 C360.2 C361.2 C362.2 C363.2 C364.2 C365.2 C366.2 C367.2 C368.2 C369.2 C370.2 C371.2 C372.2 C373.2 C374.2 C375.2 C376.2 C377.2 R145.1 R146.1 U5.A9(VSS) U5.B1(VSSQ) U5.B3(VSS) U5.B9(VSSQ) U5.D1(VSSQ) U5.D8(VSSQ) U5.E1(VSS) U5.E2(VSSQ) U5.E8(VSSQ) U5.F9(VSSQ) U5.G1(VSSQ) U5.G8(VSS) U5.G9(VSSQ) U5.J2(VSS) U5.J8(VSS) U5.M1(VSS) U5.M9(VSS) U5.P1(VSS) U5.P9(VSS) U5.T1(VSS) U5.T9(VSS) U6.A9(VSS) U6.B1(VSSQ) U6.B3(VSS) U6.B9(VSSQ) U6.D1(VSSQ) U6.D8(VSSQ) U6.E1(VSS) U6.E2(VSSQ) U6.E8(VSSQ) U6.F9(VSSQ) U6.G1(VSSQ) U6.G8(VSS) U6.G9(VSSQ) U6.J2(VSS) U6.J8(VSS) U6.M1(VSS) U6.M9(VSS) U6.P1(VSS) U6.P9(VSS) U6.T1(VSS) U6.T9(VSS)  [project net DAC_OUT0N_T1]
VK2L_DDR_1V35: C358.1 C359.1 C360.1 C361.1 C362.1 C363.1 C364.1 C365.1 C366.1 C369.1 C370.1 C371.1 C372.1 C373.1 C374.1 C375.1 C376.1 C377.1 U5.A1(VDDQ) U5.A8(VDDQ) U5.B2(VDD) U5.C1(VDDQ) U5.C9(VDDQ) U5.D2(VDDQ) U5.D9(VDD) U5.E9(VDDQ) U5.F1(VDDQ) U5.G7(VDD) U5.H2(VDDQ) U5.H9(VDDQ) U5.K2(VDD) U5.K8(VDD) U5.N1(VDD) U5.N9(VDD) U5.R1(VDD) U5.R9(VDD) U6.A1(VDDQ) U6.A8(VDDQ) U6.B2(VDD) U6.C1(VDDQ) U6.C9(VDDQ) U6.D2(VDDQ) U6.D9(VDD) U6.E9(VDDQ) U6.F1(VDDQ) U6.G7(VDD) U6.H2(VDDQ) U6.H9(VDDQ) U6.K2(VDD) U6.K8(VDD) U6.N1(VDD) U6.N9(VDD) U6.R1(VDD) U6.R9(VDD)
VK2L_DDR_VREF: C356.1 C357.1 C367.1 C368.1 U5.H1(VREFDQ) U5.M8(VREFCA) U6.H1(VREFDQ) U6.M8(VREFCA)
K2L_DDR3A0: U5.N3(A0) U6.N3(A0)
K2L_DDR3A1: U5.P7(A1) U6.P7(A1)
K2L_DDR3A2: U5.P3(A2) U6.P3(A2)
K2L_DDR3A3: U5.N2(A3) U6.N2(A3)
K2L_DDR3A4: U5.P8(A4) U6.P8(A4)
K2L_DDR3A5: U5.P2(A5) U6.P2(A5)
K2L_DDR3A6: U5.R8(A6) U6.R8(A6)
K2L_DDR3A7: U5.R2(A7) U6.R2(A7)
K2L_DDR3A8: U5.T8(A8) U6.T8(A8)
K2L_DDR3A9: U5.R3(A9) U6.R3(A9)
K2L_DDR3A10: U5.L7(A10/AP) U6.L7(A10/AP)
K2L_DDR3A11: U5.R7(A11) U6.R7(A11)
K2L_DDR3A12: U5.N7(A12/BC#) U6.N7(A12/BC#)
K2L_DDR3A13: U5.T3(A13) U6.T3(A13)
K2L_DDR3A14: U5.T7(A14) U6.T7(A14)
K2L_DDR3BA0: U5.M2(BA0) U6.M2(BA0) ; off-sheet K2L_DDR3BA0
K2L_DDR3BA1: U5.N8(BA1) U6.N8(BA1) ; off-sheet K2L_DDR3BA1
K2L_DDR3BA2: U5.M3(BA2) U6.M3(BA2) ; off-sheet K2L_DDR3BA2
K2L_DDR3CASZ: U5.K3(CAS#) U6.K3(CAS#) ; off-sheet K2L_DDR3CASZ
K2L_DDR3CE0: U5.L2(CS#) U6.L2(CS#) ; off-sheet K2L_DDR3CE0
K2L_DDR3CKE0: U5.K9(CKE) U6.K9(CKE) ; off-sheet K2L_DDR3CKE0
K2L_DDR3CLKOUTN0: U5.K7(CK#) U6.K7(CK#) ; off-sheet K2L_DDR3CLKOUTN0
K2L_DDR3CLKOUTP0: U5.J7(CK) U6.J7(CK) ; off-sheet K2L_DDR3CLKOUTP0
K2L_DDR3D32: U5.A3(DQ15)
K2L_DDR3D33: U5.B8(DQ14)
K2L_DDR3D34: U5.A2(DQ13)
K2L_DDR3D35: U5.A7(DQ12)
K2L_DDR3D36: U5.C2(DQ11)
K2L_DDR3D37: U5.C8(DQ10)
K2L_DDR3D38: U5.C3(DQ9)
K2L_DDR3D39: U5.D7(DQ8)
K2L_DDR3D40: U5.H7(DQ7)
K2L_DDR3D41: U5.G2(DQ6)
K2L_DDR3D42: U5.H8(DQ5)
K2L_DDR3D43: U5.H3(DQ4)
K2L_DDR3D44: U5.F8(DQ3)
K2L_DDR3D45: U5.F2(DQ2)
K2L_DDR3D46: U5.F7(DQ1)
K2L_DDR3D47: U5.E3(DQ0)
K2L_DDR3D48: U6.E3(DQ0)
K2L_DDR3D49: U6.F7(DQ1)
K2L_DDR3D50: U6.F2(DQ2)
K2L_DDR3D51: U6.F8(DQ3)
K2L_DDR3D52: U6.H3(DQ4)
K2L_DDR3D53: U6.H8(DQ5)
K2L_DDR3D54: U6.G2(DQ6)
K2L_DDR3D55: U6.H7(DQ7)
K2L_DDR3D56: U6.D7(DQ8)
K2L_DDR3D57: U6.C3(DQ9)
K2L_DDR3D58: U6.C8(DQ10)
K2L_DDR3D59: U6.C2(DQ11)
K2L_DDR3D60: U6.A7(DQ12)
K2L_DDR3D61: U6.A2(DQ13)
K2L_DDR3D62: U6.B8(DQ14)
K2L_DDR3D63: U6.A3(DQ15)
K2L_DDR3DQM4: U5.E7(LDM) ; off-sheet K2L_DDR3DQM4
K2L_DDR3DQM5: U5.D3(UDM) ; off-sheet K2L_DDR3DQM5
K2L_DDR3DQM6: U6.E7(LDM) ; off-sheet K2L_DDR3DQM6
K2L_DDR3DQM7: U6.D3(UDM) ; off-sheet K2L_DDR3DQM7
K2L_DDR3DQSN4: U5.G3(LDQS#) ; off-sheet K2L_DDR3DQSN4
K2L_DDR3DQSN5: U5.B7(UDQS#) ; off-sheet K2L_DDR3DQSN5
K2L_DDR3DQSN6: U6.G3(LDQS#) ; off-sheet K2L_DDR3DQSN6
K2L_DDR3DQSN7: U6.B7(UDQS#) ; off-sheet K2L_DDR3DQSN7
K2L_DDR3DQSP4: U5.F3(LDQS) ; off-sheet K2L_DDR3DQSP4
K2L_DDR3DQSP5: U5.C7(UDQS) ; off-sheet K2L_DDR3DQSP5
K2L_DDR3DQSP6: U6.F3(LDQS) ; off-sheet K2L_DDR3DQSP6
K2L_DDR3DQSP7: U6.C7(UDQS) ; off-sheet K2L_DDR3DQSP7
K2L_DDR3ODT0: U5.K1(ODT) U6.K1(ODT) ; off-sheet K2L_DDR3ODT0
K2L_DDR3RASZ: U5.J3(RAS#) U6.J3(RAS#) ; off-sheet K2L_DDR3RASZ
K2L_DDR3RESETZ: U5.T2(RESET#) U6.T2(RESET#) ; off-sheet K2L_DDR3RESETZ
K2L_DDR3WEZ: U5.L3(WE#) U6.L3(WE#) ; off-sheet K2L_DDR3WEZ
SDRAM_RZQ2: R145.2 U5.L8(ZQ)
SDRAM_RZQ3: R146.2 U6.L8(ZQ)

Not connected (* = marked no-connect by the designer): U5 J1(NC)* J9(NC)* L1(NC)* L9(NC)* M7(NC)*; U6 J1(NC)* J9(NC)* L1(NC)* L9(NC)* M7(NC)*

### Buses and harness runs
bus K2L_DDR3A[15..0]
bus K2L_DDR3D[63..0]

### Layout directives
net class Undefined: SDRAM_RZQ2, SDRAM_RZQ3

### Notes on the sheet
- K2L DDR3 SDRAM Byte-Lane 4/5
- K2L DDR3 SDRAM Byte-Lane 6/7
- All decoupling and ferrites shall be placed as close as possible to the SDRAM power pins.

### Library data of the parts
C356 C357 C367 C368 = C0603X5R0J104K030BC: as C333 on sheet k2l_soc_09
C358-C366 C369-C377 = GRM152B30J104KE19: as C332 on sheet k2l_soc_09
R145 R146 = CRCW0402240RJNED: as R140 on sheet k2l_soc_09
U5 U6 = MT41K256M16HA-125: as U3 on sheet k2l_soc_09_2

## Sheet k2l_soc_09_4.SchDoc
size 431 x 279 mm; Date: Not shown in title block; ApprovedBy: Not shown in title block; CheckedBy: Not shown in title block; Author: Not shown in title block; CompanyName: Not shown in title block; Engineer: Not shown in title block; Organization: Not shown in title block; Address1: Not shown in title block; Address2: Not shown in title block; Address3: Not shown in title block; Address4: Not shown in title block; DocumentNumber: 19; Revision: Use project parameter SCH_Rev; SheetNumber: 19; SheetTotal: 38; PageSetup: Record=PageOptions¦CenterHorizontal=True¦CenterVertical=True¦PrintScale=1.00¦XCorrection=1.00¦YCorrection=1.00¦PrintKind=0¦BorderSize=5000000¦LeftOffset=0¦BottomOffset=0¦Orientation=2¦PaperLength=1000¦PaperWidth=1000¦Scale=100¦PaperSource=15¦PrintQuality=600¦MediaType=1¦DitherType=10¦PaperKind=Letter¦PrintScaleMode=1
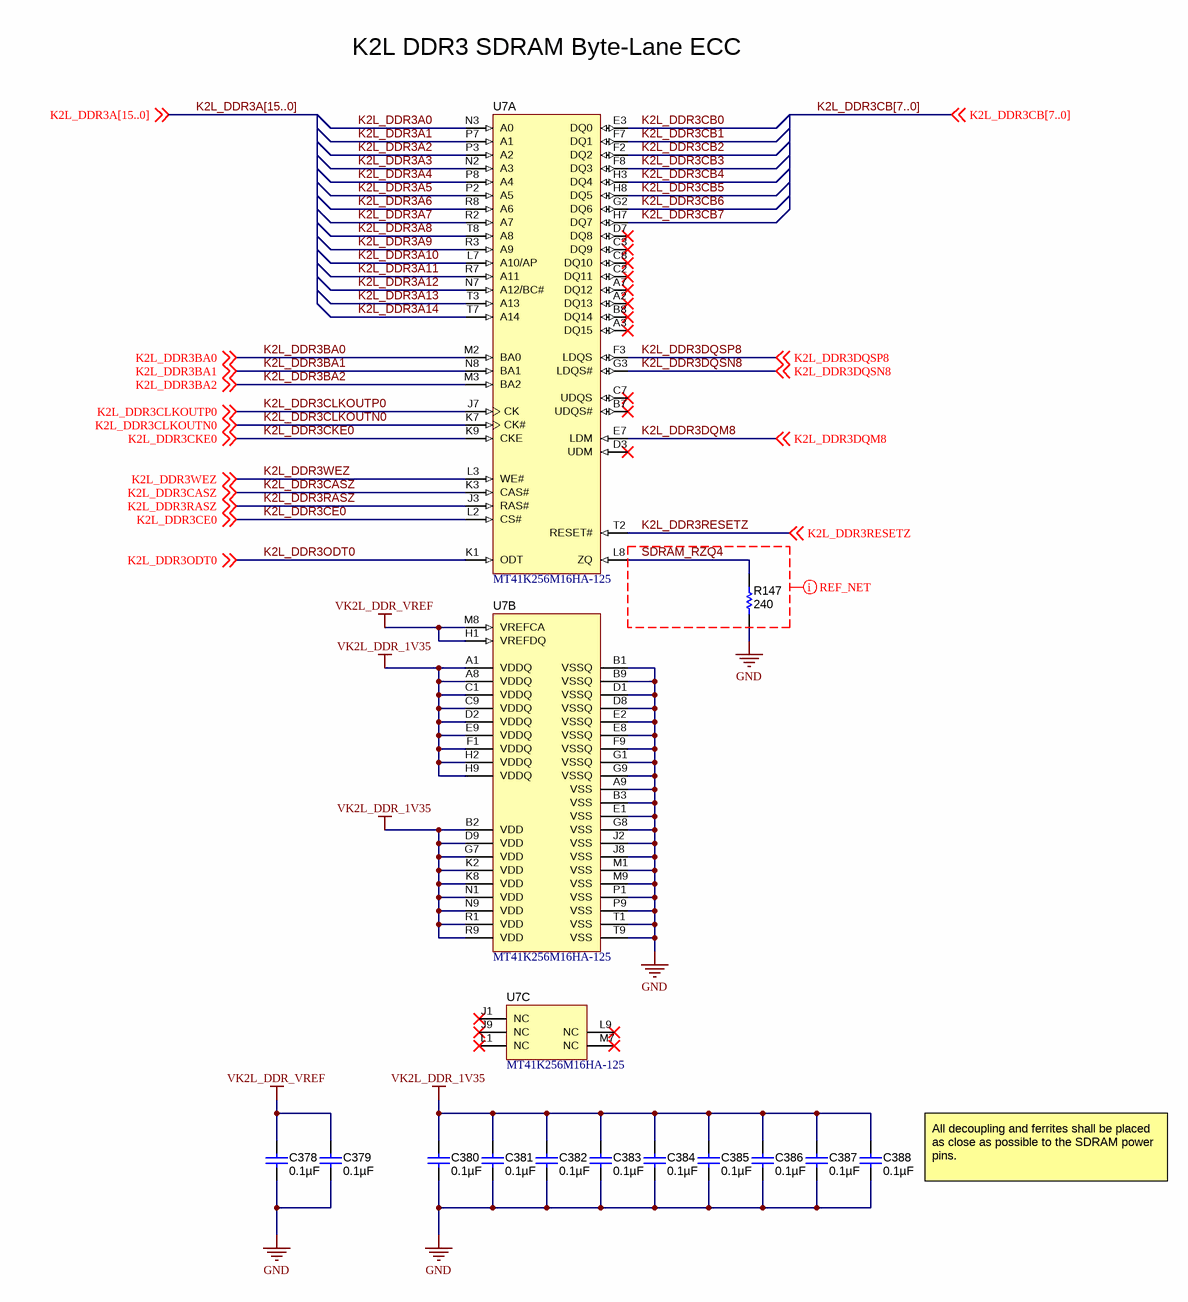
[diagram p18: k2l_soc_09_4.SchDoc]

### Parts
C378  ValueDisplayed: 0.1µF  [0201]  (hidden comment: C0603X5R0J104K030BC)
C379  ValueDisplayed: 0.1µF  [0201]  (hidden comment: C0603X5R0J104K030BC)
C380  ValueDisplayed: 0.1µF  [0402]  (hidden comment: GRM152B30J104KE19)
C381  ValueDisplayed: 0.1µF  [0402]  (hidden comment: GRM152B30J104KE19)
C382  ValueDisplayed: 0.1µF  [0402]  (hidden comment: GRM152B30J104KE19)
C383  ValueDisplayed: 0.1µF  [0402]  (hidden comment: GRM152B30J104KE19)
C384  ValueDisplayed: 0.1µF  [0402]  (hidden comment: GRM152B30J104KE19)
C385  ValueDisplayed: 0.1µF  [0402]  (hidden comment: GRM152B30J104KE19)
C386  ValueDisplayed: 0.1µF  [0402]  (hidden comment: GRM152B30J104KE19)
C387  ValueDisplayed: 0.1µF  [0402]  (hidden comment: GRM152B30J104KE19)
C388  ValueDisplayed: 0.1µF  [0402]  (hidden comment: GRM152B30J104KE19)
R147  ValueDisplayed: 240  [0402]  (hidden comment: CRCW0402240RJNED)
U7  MT41K256M16HA-125  [MICT-HA-96]  (parts A,B,C of 3)

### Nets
GND: C378.2 C379.2 C380.2 C381.2 C382.2 C383.2 C384.2 C385.2 C386.2 C387.2 C388.2 R147.1 U7.A9(VSS) U7.B1(VSSQ) U7.B3(VSS) U7.B9(VSSQ) U7.D1(VSSQ) U7.D8(VSSQ) U7.E1(VSS) U7.E2(VSSQ) U7.E8(VSSQ) U7.F9(VSSQ) U7.G1(VSSQ) U7.G8(VSS) U7.G9(VSSQ) U7.J2(VSS) U7.J8(VSS) U7.M1(VSS) U7.M9(VSS) U7.P1(VSS) U7.P9(VSS) U7.T1(VSS) U7.T9(VSS)  [project net DAC_OUT0N_T1]
VK2L_DDR_1V35: C380.1 C381.1 C382.1 C383.1 C384.1 C385.1 C386.1 C387.1 C388.1 U7.A1(VDDQ) U7.A8(VDDQ) U7.B2(VDD) U7.C1(VDDQ) U7.C9(VDDQ) U7.D2(VDDQ) U7.D9(VDD) U7.E9(VDDQ) U7.F1(VDDQ) U7.G7(VDD) U7.H2(VDDQ) U7.H9(VDDQ) U7.K2(VDD) U7.K8(VDD) U7.N1(VDD) U7.N9(VDD) U7.R1(VDD) U7.R9(VDD)
VK2L_DDR_VREF: C378.1 C379.1 U7.H1(VREFDQ) U7.M8(VREFCA)
K2L_DDR3A0: U7.N3(A0)
K2L_DDR3A1: U7.P7(A1)
K2L_DDR3A2: U7.P3(A2)
K2L_DDR3A3: U7.N2(A3)
K2L_DDR3A4: U7.P8(A4)
K2L_DDR3A5: U7.P2(A5)
K2L_DDR3A6: U7.R8(A6)
K2L_DDR3A7: U7.R2(A7)
K2L_DDR3A8: U7.T8(A8)
K2L_DDR3A9: U7.R3(A9)
K2L_DDR3A10: U7.L7(A10/AP)
K2L_DDR3A11: U7.R7(A11)
K2L_DDR3A12: U7.N7(A12/BC#)
K2L_DDR3A13: U7.T3(A13)
K2L_DDR3A14: U7.T7(A14)
K2L_DDR3BA0: U7.M2(BA0) ; off-sheet K2L_DDR3BA0
K2L_DDR3BA1: U7.N8(BA1) ; off-sheet K2L_DDR3BA1
K2L_DDR3BA2: U7.M3(BA2) ; off-sheet K2L_DDR3BA2
K2L_DDR3CASZ: U7.K3(CAS#) ; off-sheet K2L_DDR3CASZ
K2L_DDR3CB0: U7.E3(DQ0)
K2L_DDR3CB1: U7.F7(DQ1)
K2L_DDR3CB2: U7.F2(DQ2)
K2L_DDR3CB3: U7.F8(DQ3)
K2L_DDR3CB4: U7.H3(DQ4)
K2L_DDR3CB5: U7.H8(DQ5)
K2L_DDR3CB6: U7.G2(DQ6)
K2L_DDR3CB7: U7.H7(DQ7)
K2L_DDR3CE0: U7.L2(CS#) ; off-sheet K2L_DDR3CE0
K2L_DDR3CKE0: U7.K9(CKE) ; off-sheet K2L_DDR3CKE0
K2L_DDR3CLKOUTN0: U7.K7(CK#) ; off-sheet K2L_DDR3CLKOUTN0
K2L_DDR3CLKOUTP0: U7.J7(CK) ; off-sheet K2L_DDR3CLKOUTP0
K2L_DDR3DQM8: U7.E7(LDM) ; off-sheet K2L_DDR3DQM8
K2L_DDR3DQSN8: U7.G3(LDQS#) ; off-sheet K2L_DDR3DQSN8
K2L_DDR3DQSP8: U7.F3(LDQS) ; off-sheet K2L_DDR3DQSP8
K2L_DDR3ODT0: U7.K1(ODT) ; off-sheet K2L_DDR3ODT0
K2L_DDR3RASZ: U7.J3(RAS#) ; off-sheet K2L_DDR3RASZ
K2L_DDR3RESETZ: U7.T2(RESET#) ; off-sheet K2L_DDR3RESETZ
K2L_DDR3WEZ: U7.L3(WE#) ; off-sheet K2L_DDR3WEZ
SDRAM_RZQ4: R147.2 U7.L8(ZQ)

Not connected (* = marked no-connect by the designer): U7 A2(DQ13)* A3(DQ15)* A7(DQ12)* B7(UDQS#)* B8(DQ14)* C2(DQ11)* C3(DQ9)* C7(UDQS)* C8(DQ10)* D3(UDM)* D7(DQ8)* J1(NC)* J9(NC)* L1(NC)* L9(NC)* M7(NC)*

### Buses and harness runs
bus K2L_DDR3A[15..0]
bus K2L_DDR3CB[7..0]

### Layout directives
net class Undefined: SDRAM_RZQ4

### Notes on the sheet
- K2L DDR3 SDRAM Byte-Lane ECC
- All decoupling and ferrites shall be placed as close as possible to the SDRAM power pins.

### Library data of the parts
C378 C379 = C0603X5R0J104K030BC: as C333 on sheet k2l_soc_09
C380-C388 = GRM152B30J104KE19: as C332 on sheet k2l_soc_09
R147 = CRCW0402240RJNED: as R140 on sheet k2l_soc_09
U7 = MT41K256M16HA-125: as U3 on sheet k2l_soc_09_2

## Sheet k2l_soc_10.SchDoc
size 431 x 279 mm; Date: Not shown in title block; ApprovedBy: Not shown in title block; CheckedBy: Not shown in title block; Author: Not shown in title block; CompanyName: Not shown in title block; Engineer: Not shown in title block; Organization: Not shown in title block; Address1: Not shown in title block; Address2: Not shown in title block; Address3: Not shown in title block; Address4: Not shown in title block; DocumentNumber: 20; Revision: Use project parameter SCH_Rev; SheetNumber: 20; SheetTotal: 38; PageSetup: Record=PageOptions¦CenterHorizontal=True¦CenterVertical=True¦PrintScale=1.00¦XCorrection=1.00¦YCorrection=1.00¦PrintKind=0¦BorderSize=5000000¦LeftOffset=0¦BottomOffset=0¦Orientation=2¦PaperLength=1000¦PaperWidth=1000¦Scale=100¦PaperSource=15¦PrintQuality=600¦MediaType=1¦DitherType=10¦PaperKind=Letter¦PrintScaleMode=1
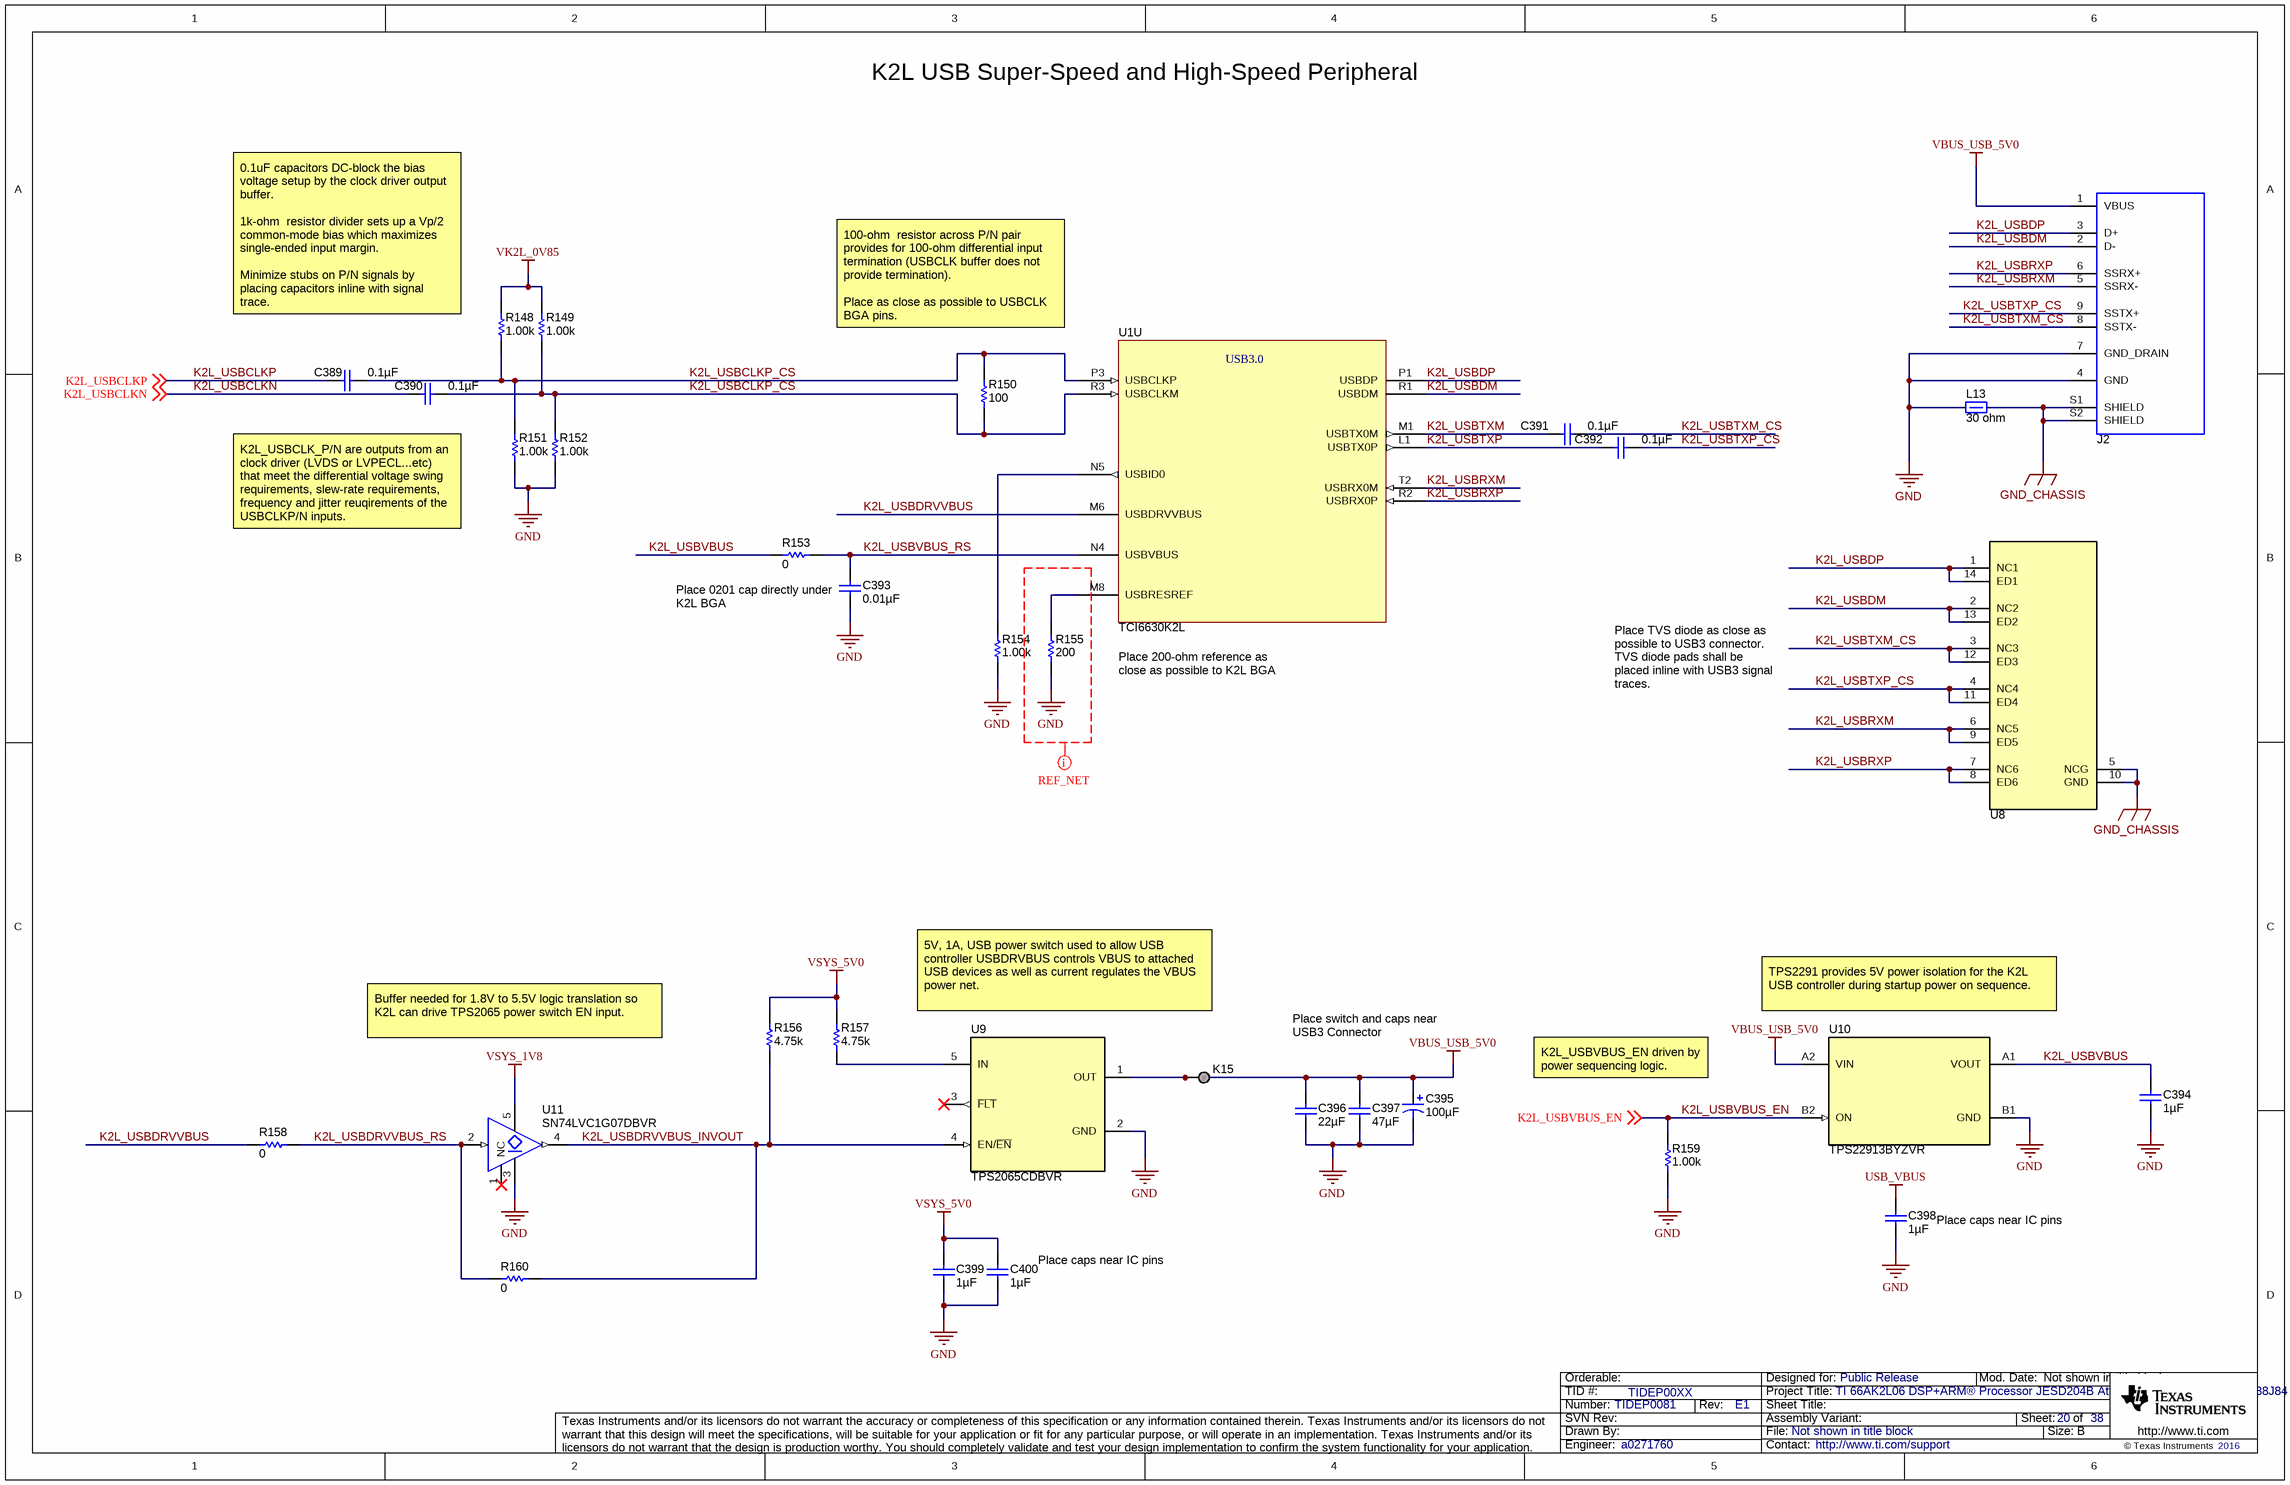
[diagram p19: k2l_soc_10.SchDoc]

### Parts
C389  ValueDisplayed: 0.1µF  [0402]  (hidden comment: GCM155R7IC104KA55D)
C390  ValueDisplayed: 0.1µF  [0402]  (hidden comment: GCM155R7IC104KA55D)
C391  ValueDisplayed: 0.1µF  [0201L]  (hidden comment: CL03A104KP3NNNC)
C392  ValueDisplayed: 0.1µF  [0201L]  (hidden comment: CL03A104KP3NNNC)
C393  ValueDisplayed: 0.01µF  [0201]  (hidden comment: GRM033R60J103KA01D)
C394  ValueDisplayed: 1µF  [0603]  (hidden comment: GRM188R70J105KA01D)
C395  ValueDisplayed: 100µF  [6032-28]  (hidden comment: 293D107X9010C2TE3)
C396  ValueDisplayed: 22µF  [0805_HV]  (hidden comment: GRM21BC80G226ME39L)
C397  ValueDisplayed: 47µF  [0805_HV]  (hidden comment: GRM21BR60J476ME15L)
C398  ValueDisplayed: 1µF  [0603]  (hidden comment: GRM188R70J105KA01D)
C399  ValueDisplayed: 1µF  [0603]  (hidden comment: GRM188R70J105KA01D)
C400  ValueDisplayed: 1µF  [0603]  (hidden comment: GRM188R70J105KA01D)
J2  GSB4111312HR  [Amphenol_GSB4111312HR]  (value not drawn)
K15  TESTPOINT  [TESTPOINT]  (value not drawn)  (no BOM)
L13  value 30 ohm  [0805_HV]  (hidden comment: MPZ2012S300AT000)
R148  ValueDisplayed: 1.00k  [0402]  (hidden comment: CRCW04021K00FKED)
R149  ValueDisplayed: 1.00k  [0402]  (hidden comment: CRCW04021K00FKED)
R150  ValueDisplayed: 100  [0201M]  (hidden comment: ERJ-1GEF1000C)
R151  ValueDisplayed: 1.00k  [0402]  (hidden comment: CRCW04021K00FKED)
R152  ValueDisplayed: 1.00k  [0402]  (hidden comment: CRCW04021K00FKED)
R153  ValueDisplayed: 0  [0402]  (hidden comment: CRCW04020000Z0ED)
R154  ValueDisplayed: 1.00k  [0402]  (hidden comment: CRCW04021K00FKED)
R155  ValueDisplayed: 200  [0805_HV]  (hidden comment: RG2012P-201-B-T5)
R156  ValueDisplayed: 4.75k  [0402]  (hidden comment: CRCW04024K75FKED)
R157  ValueDisplayed: 4.75k  [0402]  (hidden comment: CRCW04024K75FKED)
R158  ValueDisplayed: 0  [0402]  (hidden comment: CRCW04020000Z0ED)
R159  ValueDisplayed: 1.00k  [0402]  (hidden comment: CRCW04021K00FKED)
R160  ValueDisplayed: 0  [0402]  (hidden comment: CRCW04020000Z0ED)
U1  TCI6630K2L  [BGA900C80P30X30_2500X2500X355]  (part U of 24)
U8  SP3012-06UTG  [UDFN-14]  (value not drawn)
U9  TPS2065CDBVR  [DBV0005A_N]
U10  TPS22913BYZVR  [YZV0004ADAD]
U11  SN74LVC1G07DBVR  [DBV0005A_N]

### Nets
GND: C393.2 C394.2 C395.2(-) C396.2 C397.2 C398.2 C399.2 C400.2 J2.4(GND) J2.7(GND_DRAIN) L13.1 R151.1 R152.1 R154.1 R155.1 R159.1 U9.2(GND) U10.B1(GND) U11.3(GND)  [project net DAC_OUT0N_T1]
GND_CHASSIS: J2.S1(SHIELD) J2.S2(SHIELD) L13.2 U8.5(NCG) U8.10(GND)
USB_VBUS: C398.1
VBUS_USB_5V0: C395.1(+) C396.1 C397.1 J2.1(VBUS) K15.1 U9.1(OUT) U10.A2(VIN)
VK2L_0V85: R148.2 R149.2
VSYS_1V8: U11.5(VCC)
VSYS_5V0: C399.1 C400.1 R156.2 R157.2
K2L_USBCLKN: C390.2 ; off-sheet K2L_USBCLKN  [project net K2L_DDR3ACLKN]
K2L_USBCLKP: C389.2 ; off-sheet K2L_USBCLKP  [project net K2L_DDR3ACLKP]
K2L_USBCLKP_CS: C389.1 C390.1 R148.1 R149.1 R150.1 R150.2 R151.2 R152.2 U1.P3(USBCLKP) U1.R3(USBCLKM)
K2L_USBDM: J2.2(D-) U1.R1(USBDM) U8.2(NC2) U8.13(ED2)
K2L_USBDP: J2.3(D+) U1.P1(USBDP) U8.1(NC1) U8.14(ED1)
K2L_USBDRVVBUS: R158.1 U1.M6(USBDRVVBUS)
K2L_USBDRVVBUS_INVOUT: R156.1 R160.2 U9.4(EN/~{EN}) U11.4(Y)
K2L_USBDRVVBUS_RS: R158.2 R160.1 U11.2(A)
K2L_USBRXM: J2.5(SSRX-) U1.T2(USBRX0M) U8.6(NC5) U8.9(ED5)
K2L_USBRXP: J2.6(SSRX+) U1.R2(USBRX0P) U8.7(NC6) U8.8(ED6)
K2L_USBTXM: C391.2 U1.M1(USBTX0M)
K2L_USBTXM_CS: C391.1 J2.8(SSTX-) U8.3(NC3) U8.12(ED3)
K2L_USBTXP: C392.2 U1.L1(USBTX0P)
K2L_USBTXP_CS: C392.1 J2.9(SSTX+) U8.4(NC4) U8.11(ED4)
K2L_USBVBUS: C394.1 R153.1 U10.A1(VOUT)
K2L_USBVBUS_EN: R159.2 U10.B2(ON) ; off-sheet K2L_USBVBUS_EN
K2L_USBVBUS_RS: C393.1 R153.2 U1.N4(USBVBUS)
NetR154_2: R154.2 U1.N5(USBID0)
NetR155_2: R155.2 U1.M8(USBRESREF)
NetR157_1: R157.1 U9.5(IN)

Not connected (* = marked no-connect by the designer): U9 3(~{FLT})*; U11 1(NC)*

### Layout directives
net class Undefined: GND

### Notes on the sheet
- K2L USB Super-Speed and High-Speed Peripheral
- (near R148) 0.1uF capacitors DC-block the bias voltage setup by the clock driver output buffer.
  1k-ohm  resistor divider sets up a Vp/2 common-mode bias which maximizes single-ended input margin.
  Minimize stubs on P/N signals by placing capacitors inline with signal trace.
- 100-ohm  resistor across P/N pair provides for 100-ohm differential input termination (USBCLK buffer does not provide termination).
  Place as close as possible to USBCLK BGA pins.
- K2L_USBCLK_P/N are outputs from an clock driver (LVDS or LVPECL...etc) that meet the differential voltage swing requirements, slew-rate requirements, frequency and jitter reuqirements of the USBCLKP/N inputs.
- (near C393) Place 0201 cap directly under K2L BGA
- Place 200-ohm reference as close as possible to K2L BGA
- Place TVS diode as close as possible to USB3 connector.
  TVS diode pads shall be placed inline with USB3 signal traces.
- Buffer needed for 1.8V to 5.5V logic translation so K2L can drive TPS2065 power switch EN input.
- 5V, 1A, USB power switch used to allow USB controller USBDRVBUS controls VBUS to attached USB devices as well as current regulates the VBUS power net.
- Place switch and caps near USB3 Connector
- TPS2291 provides 5V power isolation for the K2L USB controller during startup power on sequence.
- K2L_USBVBUS_EN driven by power sequencing logic.
- (near C398) Place caps near IC pins
- (near C400) Place caps near IC pins

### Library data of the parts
C389 C390 = GCM155R7IC104KA55D: CAP, CERM, 0.1 µF, 16 V, +/- 10%, X7R, 0402; Manufacturer: MuRata; Polarized: N; CompType: Capacitor; Value: 0.1uF; U/M: EA; Cap_F: 0.0000001; Tolerance_%: 10; Value1: Unknown; VDC_V: 16; Value2: 16V; TaMin_C: -55; TaMax_C: 125
C391 C392 = CL03A104KP3NNNC: CAP, CERM, 0.1 µF, 10 V, +/- 10%, X5R, 0201; Manufacturer: Samsung; Polarized: N; CompType: Capacitor; Value: 0.1uF; U/M: EA; Cap_F: 0.0000001; Tolerance_%: 10; Value1: Unknown; Value2: 10V; TaMin_C: -55; TaMax_C: 85; Cap_Case: 0201
C393 = GRM033R60J103KA01D: CAP, CERM, 0.01 µF, 6.3 V, +/- 10%, X5R, 0201; Manufacturer: MuRata; Polarized: N; CompType: Capacitor; Value: 0.01uF; U/M: EA; Cap_F: 0.00000001; Tolerance_%: 10; Value1: Unknown; VDC_V: 6.3; Value2: 6.3V; TaMin_C: -55; TaMax_C: 85; SizeArea_mm2: 0.18; SizeAreaWB_mm2: 2.08; SizeX_mm: 0.6; SizeY_mm: 0.3; SizeZ_mm: 0.26; AEC Category: Q200
C394 C398-C400 = GRM188R70J105KA01D: CAP, CERM, 1 µF, 6.3 V, +/- 10%, X7R, 0603; Manufacturer: MuRata; Polarized: N; CompType: Capacitor; Value: 1uF; U/M: EA; Cap_F: 0.000001; Tolerance_%: 10; Value1: Unknown; VDC_V: 6.3; Value2: 6.3V; TaMin_C: -55; TaMax_C: 125; SizeArea_mm2: 1.28; SizeAreaWB_mm2: 4.68; SizeX_mm: 1.6; SizeY_mm: 0.8; SizeZ_mm: 1; AEC Category: Q200
C395 = 293D107X9010C2TE3: CAP, TA, 100 µF, 10 V, +/- 10%, 0.9 ohm, SMD; Manufacturer: Vishay-Sprague; Polarized: Y; CompType: Capacitor; Value: 100uF; U/M: EA; Cap_F: 0.0001; Tolerance_%: 10; Value1: 0.9 ohm; Value2: 10V; ESR_ohm: 0.9; IRMS_A: 0.35; TaMin_C: -55; TaMax_C: 125; Cap_Case: C; AEC Category: Q200
C396 = GRM21BC80G226ME39L: CAP, CERM, 22 µF, 4 V, +/- 20%, X6S, 0805; Manufacturer: MuRata; Polarized: N; CompType: Capacitor; Value: 22uF; U/M: EA; Cap_F: 0.000022; Tolerance_%: 20; Value1: Unknown; VDC_V: 4; Value2: 4V; TaMin_C: -55; TaMax_C: 105; Cap_Case: 0805; SizeArea_mm2: 2.5; SizeAreaWB_mm2: 6.75; SizeX_mm: 2; SizeY_mm: 1.25; SizeZ_mm: 1.45; AEC Category: Q200
C397 = GRM21BR60J476ME15L: CAP, CERM, 47 µF, 6.3 V, +/- 20%, X5R, 0805; Manufacturer: MuRata; Polarized: N; CompType: Capacitor; Value: 47uF; U/M: EA; Cap_F: 0.000047; Tolerance_%: 20; Value1: Unknown; VDC_V: 6.3; Value2: 6.3V; TaMin_C: -55; TaMax_C: 85; Cap_Case: 0805; SizeArea_mm2: 2.5; SizeAreaWB_mm2: 6.75; SizeX_mm: 2; SizeY_mm: 1.25; SizeZ_mm: 1.45; AEC Category: Q200
J2 = GSB4111312HR: Connector, Receptacle, USB 3.1 Type A, R/A, TH; Manufacturer: Amphenol Canada; SymbolCreator: Altium; Pitch_mm: 2; Gender: Female; RowSpacing_mm: 1.5; ContactFinish: Gold
K15 = TESTPOINT: TEST POINT.  No entry in BOM.
L13 = MPZ2012S300AT000: Ferrite Bead, 30 ohm @ 100 MHz, 6 A, 0805; Manufacturer: TDK; Imax_A: 6; DCR_ohm: 0.01; Value1: 0.01 ohm; Value2: 6A; ZTyp@100MHz_Ohm: 30
R148 R149 R151 R152 R154 R159 = CRCW04021K00FKED: RES, 1.00 k, 1%, 0.063 W, 0402; Manufacturer: Vishay-Dale; CompType: Resistor; Value: 1.00k; Res_ohm: 1000; Value_Code: 1k00; Tolerance_%: 1; Power_W: 0.063; Value2: 0.063W; VDC_V: 50; TempCo: 100 ppm/C; EIA_Code: E96; U/M: EA
R150 = ERJ-1GEF1000C: RES, 100, 1%, 0.05 W, 0201; Manufacturer: Panasonic; CompType: Resistor; Value: 100; Value_Code: 100R; Tolerance_%: 1; Power_W: 0.05; Value2: 0.05W; VDC_V: 25; TempCo: 200 ppm/C; SizeArea_mm2: 0.18; SizeAreaWB_mm2: 2.08; SizeX_mm: 0.6; SizeY_mm: 0.3; SizeZ_mm: 0.26; EIA_Code: E96; U/M: EA; AEC Category: Q200
R153 R158 R160 = CRCW04020000Z0ED: RES, 0, 5%, 0.063 W, 0402; Manufacturer: Vishay-Dale; CompType: Resistor; Value: 0; Value_Code: 0000; Tolerance_%: 5; Power_W: 0.063; Value2: 0.063W; VDC_V: 50; TempCo: 200 ppm/C; SizeArea_mm2: 0.5; SizeX_mm: 1; SizeZ_mm: 0.6; EIA_Code: E24; U/M: EA; AEC Category: Q200
R155 = RG2012P-201-B-T5: RES, 200, 0.1%, 0.125 W, 0805; Manufacturer: Susumu Co Ltd; CompType: Resistor; Value: 200; Value_Code: 200R; Tolerance_%: 0.1; Power_W: 0.125; Value2: 0.125W; VDC_V: 100; TempCo: 25 ppm/C; EIA_Code: E192; U/M: EA
R156 R157 = CRCW04024K75FKED: RES, 4.75 k, 1%, 0.063 W, 0402; Manufacturer: Vishay-Dale; CompType: Resistor; Value: 4.75k; Res_ohm: 4750; Value_Code: 4k75; Tolerance_%: 1; Power_W: 0.063; Value2: 0.063W; VDC_V: 50; TempCo: 100 ppm/C; EIA_Code: E96; U/M: EA
U1 = lamarr_soc_TCI6630K2L: as U1 on sheet k2l_soc_09
U8 = SP3012-06UTG: TVS DIODE 5VWM 7VC 14UDFN; Manufacturer: Littelfuse Inc.; SymbolCreator: a0271760; CompType: TVS - Diodes; U/M: EA, IN, or GM
U9 = TPS2065CDBVR: Current-Limited, Power-Distribution Switches, DBV0005A; Alternate PartNumber: TPS2065CDBVT; Manufacturer: Texas Instruments; SymbolCreator: x0208326; SizeArea_mm2: 8.12; SizeAreaWB_mm2: 14.82; SizeX_mm: 2.8; SizeY_mm: 2.9; SizeZ_mm: 1.45; CompType: IC; U/M: EA
U10 = TPS22913BYZVR: Ultra-small, Low On Resistance Load Switch with Controlled Turn-on, YZV0004ADAD; Alternate PartNumber: TPS22913BYZVT; Manufacturer: Texas Instruments; SymbolCreator: a0799628; SizeArea_mm2: 1.5625; SizeAreaWB_mm2: 5.0625; SizeX_mm: 1.25; SizeZ_mm: 0.5; CompType: IC; U/M: EA
U11 = SN74LVC1G07DBVR: SINGLE BUFFER/DRIVER WITH OPEN-DRAIN OUTPUT, DBV0005A; Alternate PartNumber: SN74LVC1G07DBVT; Manufacturer: Texas Instruments; SymbolCreator: a0411947; SizeArea_mm2: 8.12; SizeAreaWB_mm2: 14.82; SizeX_mm: 2.8; SizeY_mm: 2.9; SizeZ_mm: 1.45; CompType: IC; U/M: EA

## Sheet k2l_soc_12.SchDoc
size 431 x 279 mm; Date: Not shown in title block; ApprovedBy: Not shown in title block; CheckedBy: Not shown in title block; Author: Not shown in title block; CompanyName: Not shown in title block; Engineer: Not shown in title block; Organization: Not shown in title block; Address1: Not shown in title block; Address2: Not shown in title block; Address3: Not shown in title block; Address4: Not shown in title block; DocumentNumber: 21; Revision: Use project parameter SCH_Rev; SheetNumber: 21; SheetTotal: 38; PageSetup: Record=PageOptions¦CenterHorizontal=True¦CenterVertical=True¦PrintScale=1.00¦XCorrection=1.00¦YCorrection=1.00¦PrintKind=0¦BorderSize=5000000¦LeftOffset=0¦BottomOffset=0¦Orientation=2¦PaperLength=1000¦PaperWidth=1000¦Scale=100¦PaperSource=15¦PrintQuality=600¦MediaType=1¦DitherType=10¦PaperKind=Letter¦PrintScaleMode=1
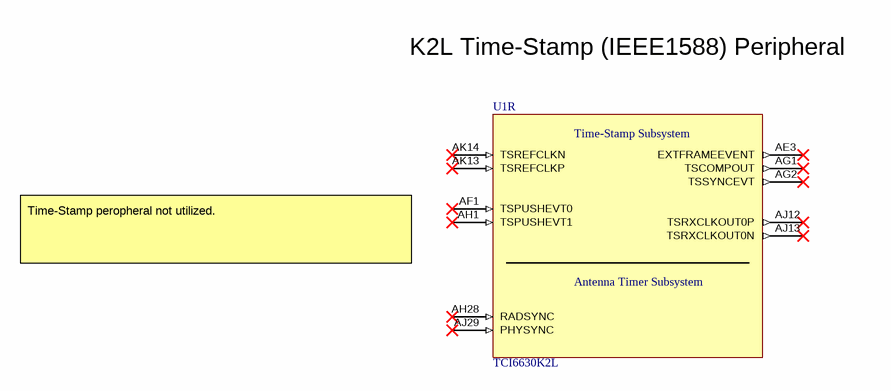
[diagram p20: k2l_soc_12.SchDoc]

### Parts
U1  TCI6630K2L  [BGA900C80P30X30_2500X2500X355]  (part R of 24)

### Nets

Not connected (* = marked no-connect by the designer): U1 AE3(EXTFRAMEEVENT)* AF1(TSPUSHEVT0)* AG1(TSCOMPOUT)* AG2(TSSYNCEVT)* AH1(TSPUSHEVT1)* AH28(RADSYNC)* AJ12(TSRXCLKOUT0P)* AJ13(TSRXCLKOUT0N)* AJ29(PHYSYNC)* AK13(TSREFCLKP)* AK14(TSREFCLKN)*

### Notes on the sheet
- K2L Time-Stamp (IEEE1588) Peripheral
- Time-Stamp peropheral not utilized.

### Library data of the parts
U1 = lamarr_soc_TCI6630K2L: as U1 on sheet k2l_soc_09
